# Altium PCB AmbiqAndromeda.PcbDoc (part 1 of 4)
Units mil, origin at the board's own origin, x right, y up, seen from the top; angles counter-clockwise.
Board outline 4055.04 x 2407.2 mil, 6 copper layers (Layer 1, Layer 2, Layer 3, Layer 4, Layer 5, Layer 6), stack 76.457 mil thick; 255 components, 215 nets, 1186 pads, 683 vias.
Unrouted connection lines stored in the file: 258.
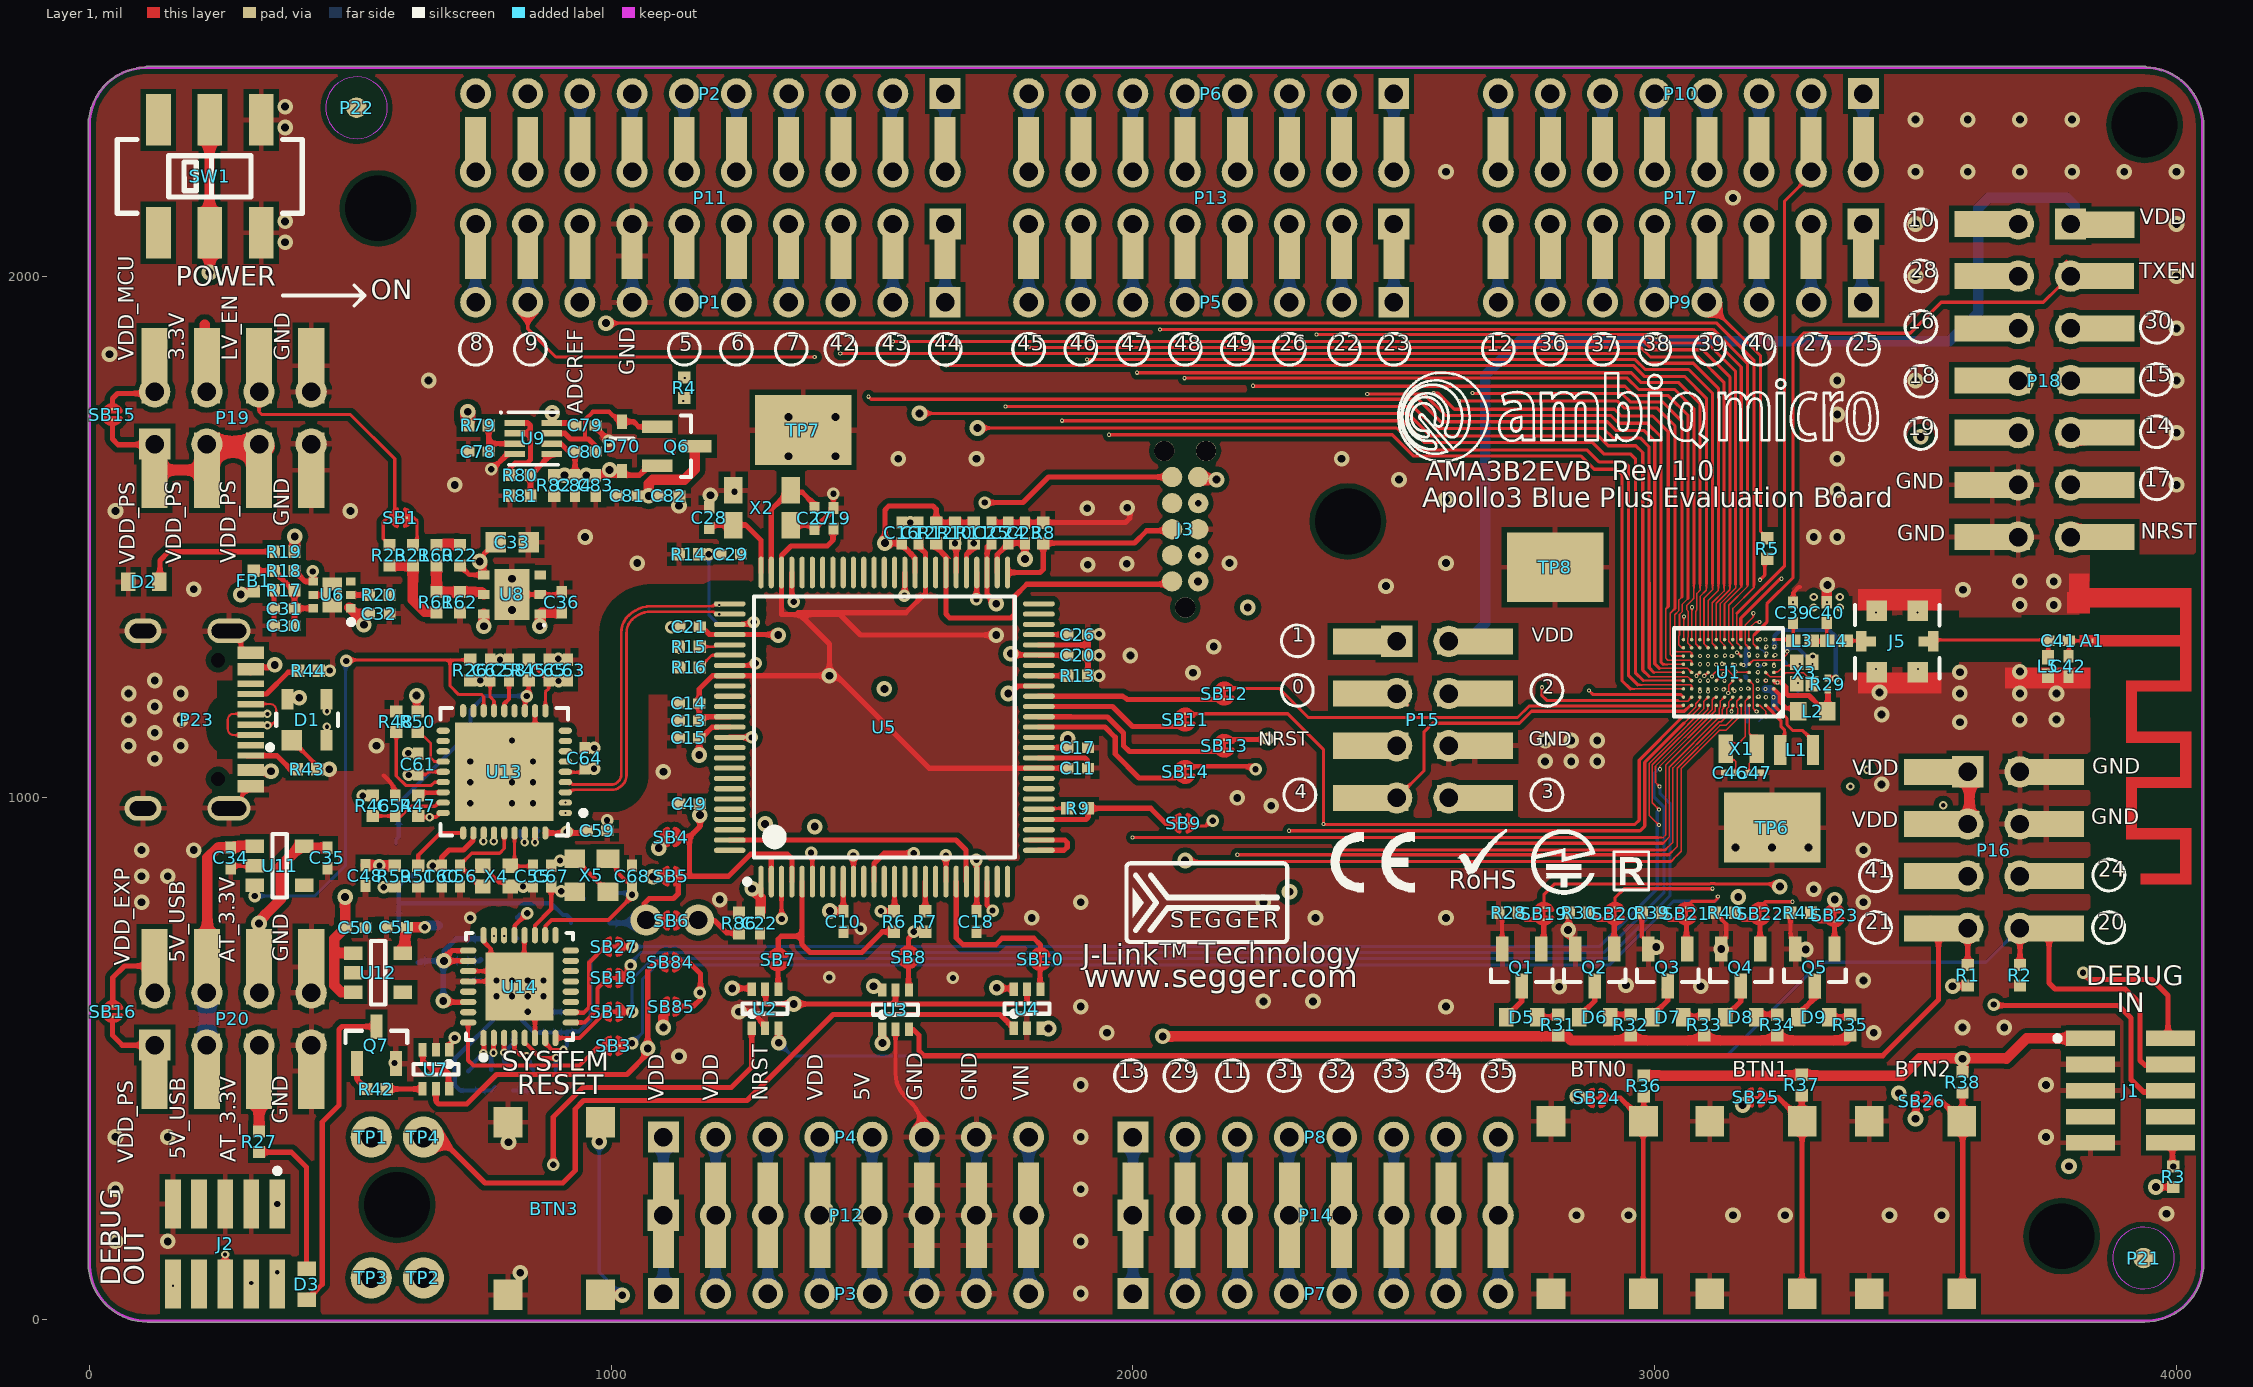
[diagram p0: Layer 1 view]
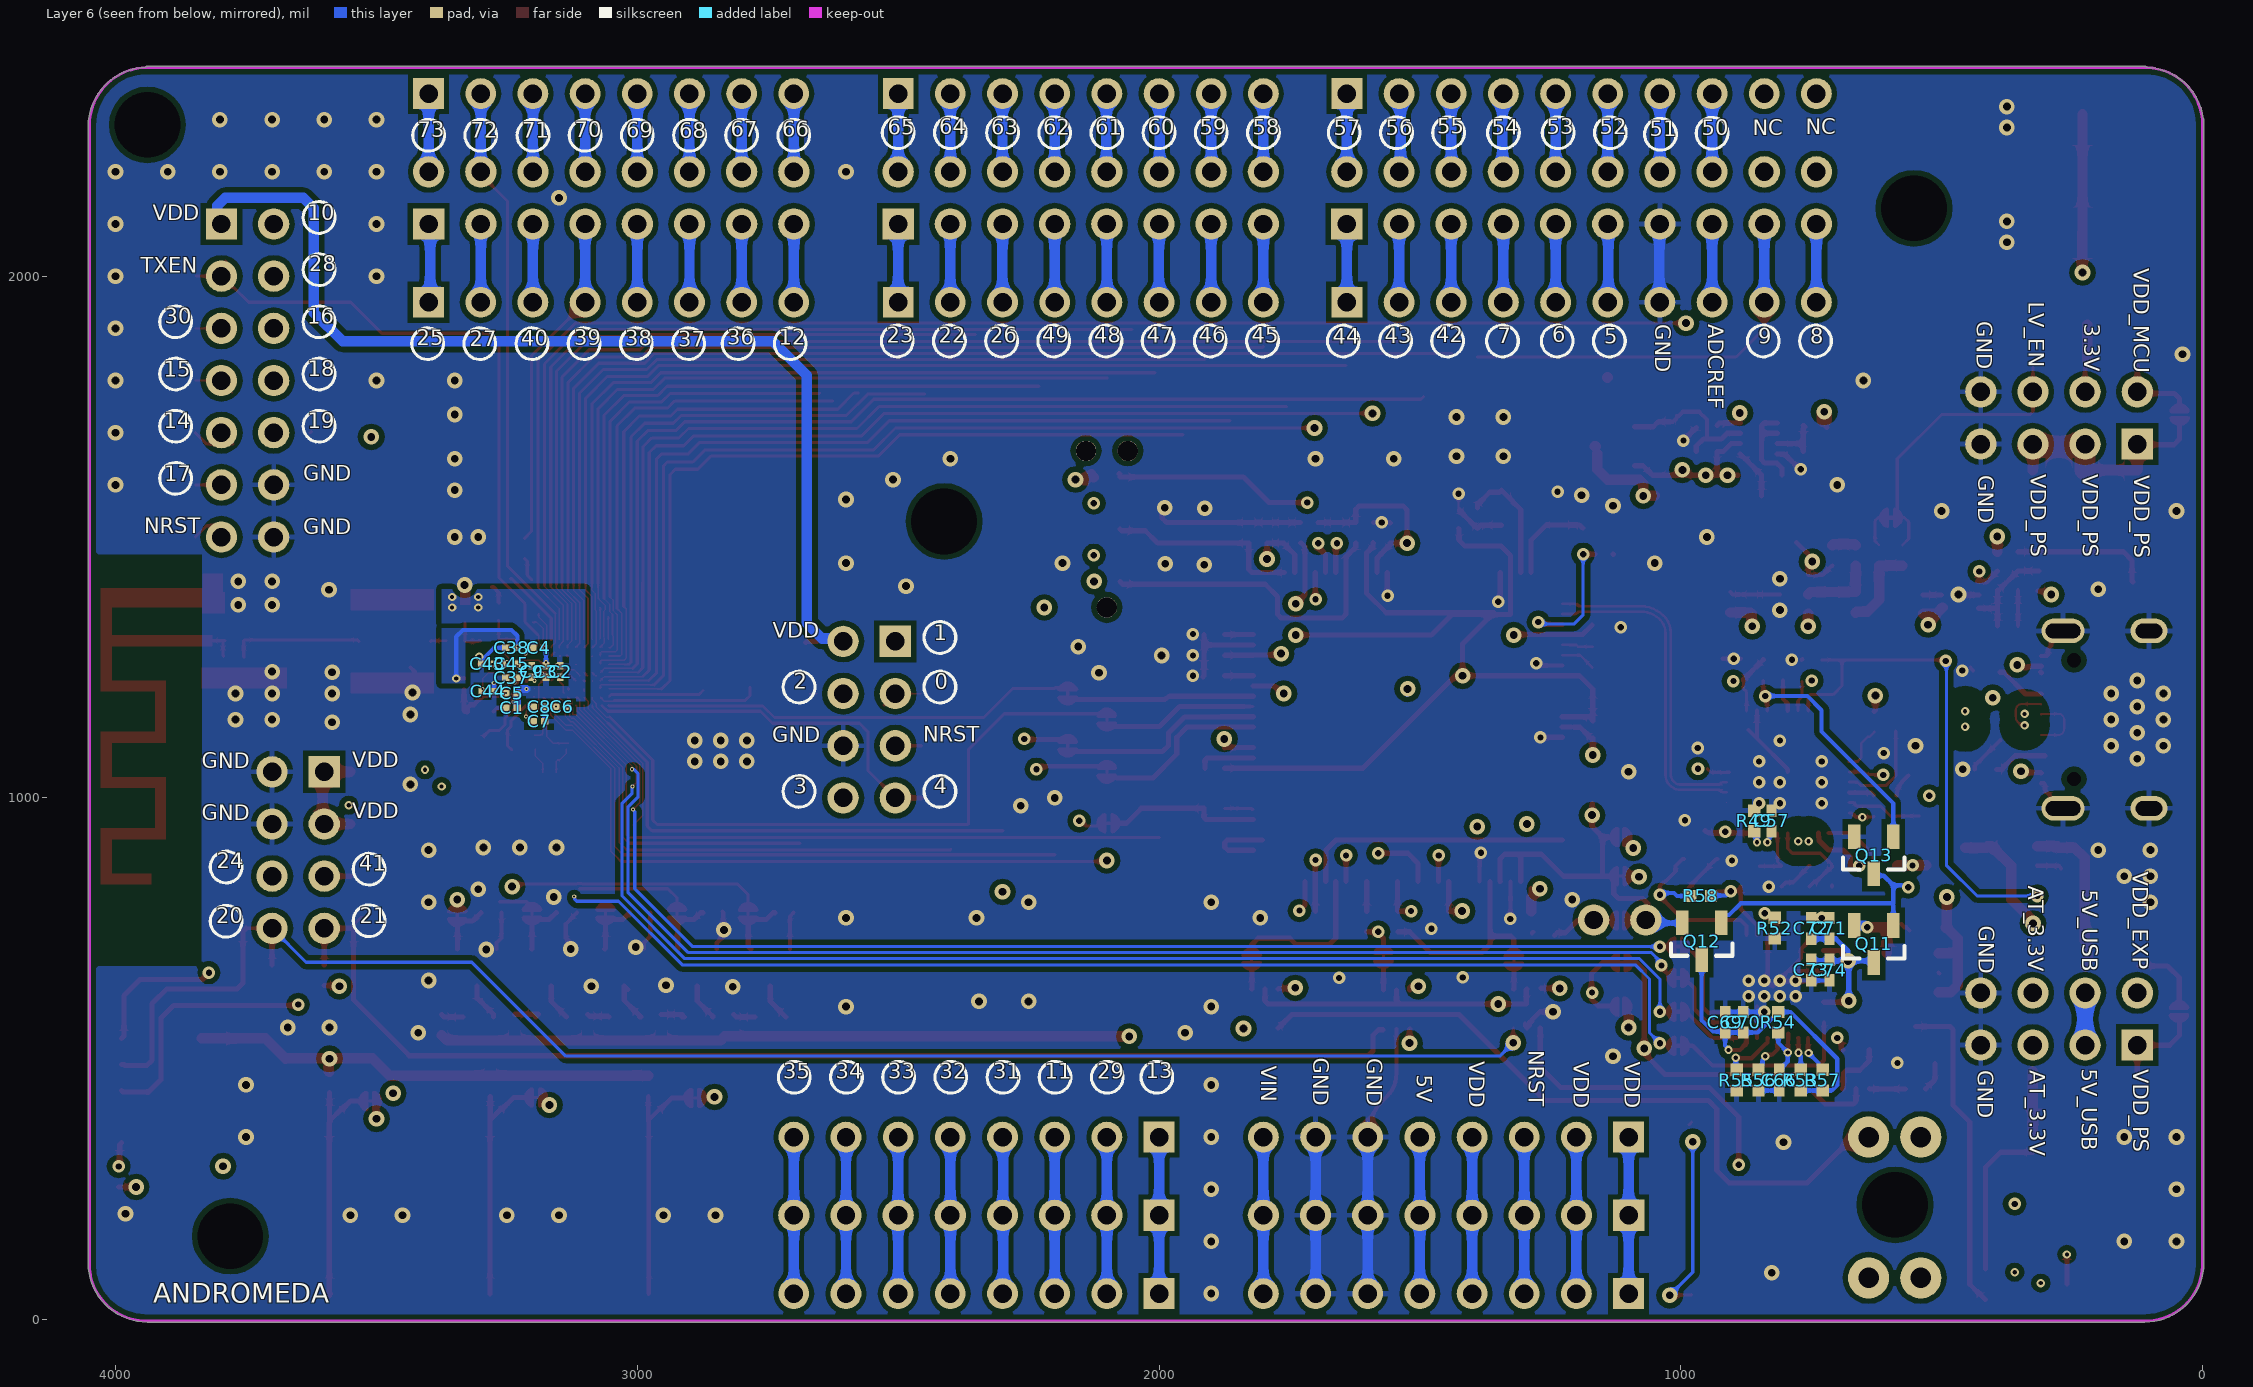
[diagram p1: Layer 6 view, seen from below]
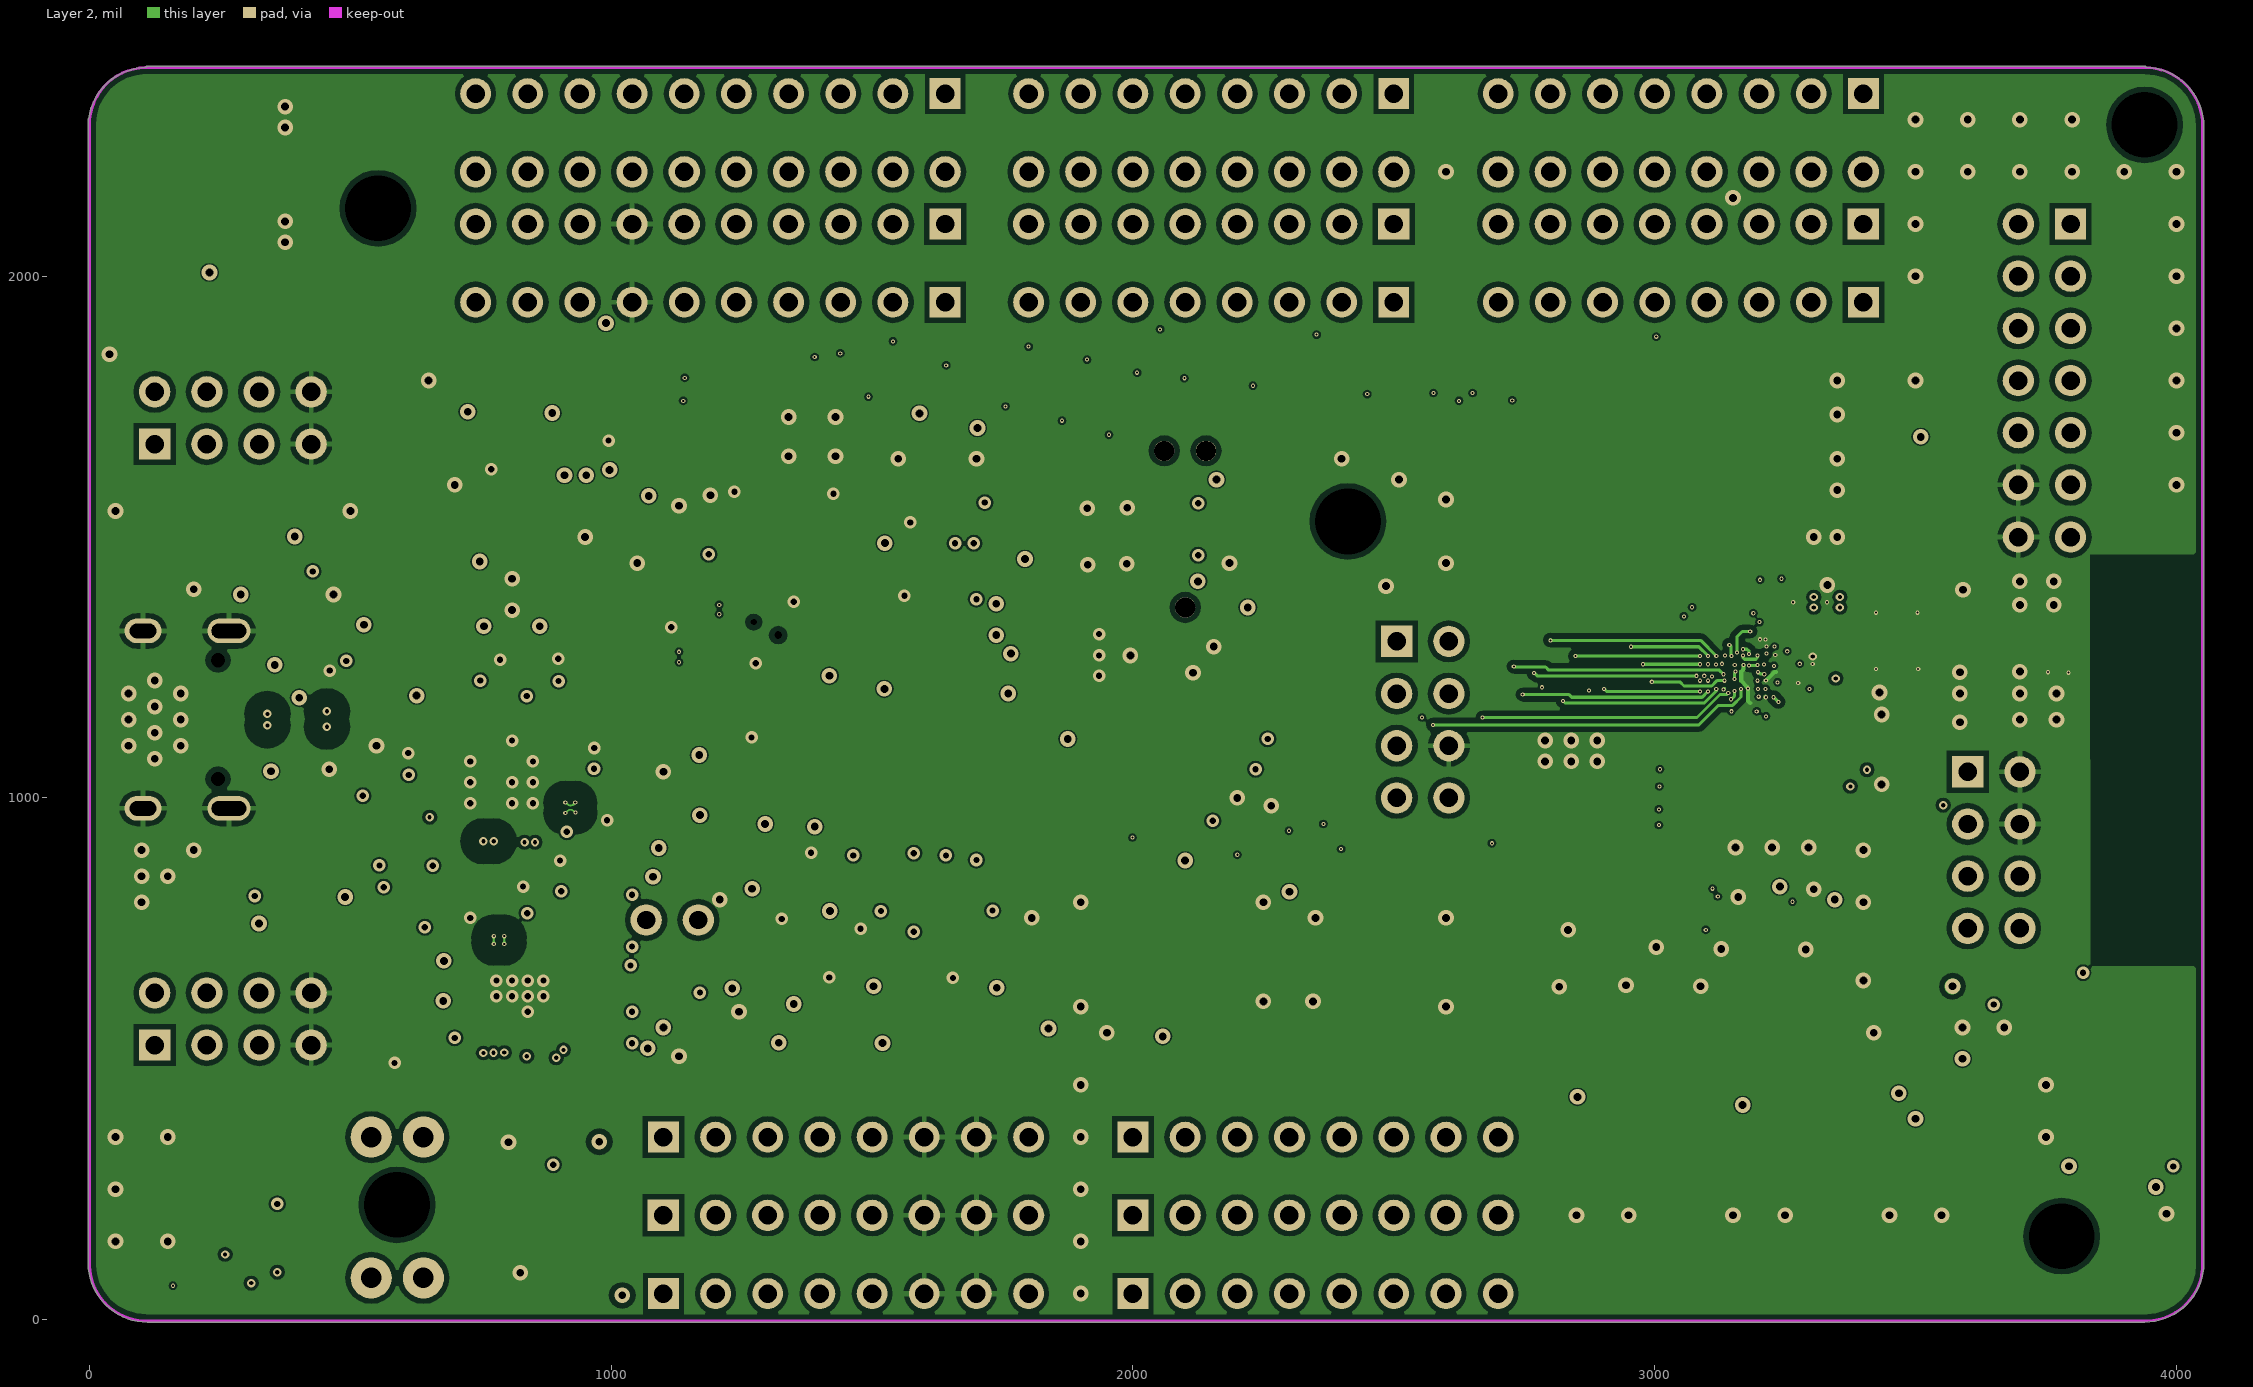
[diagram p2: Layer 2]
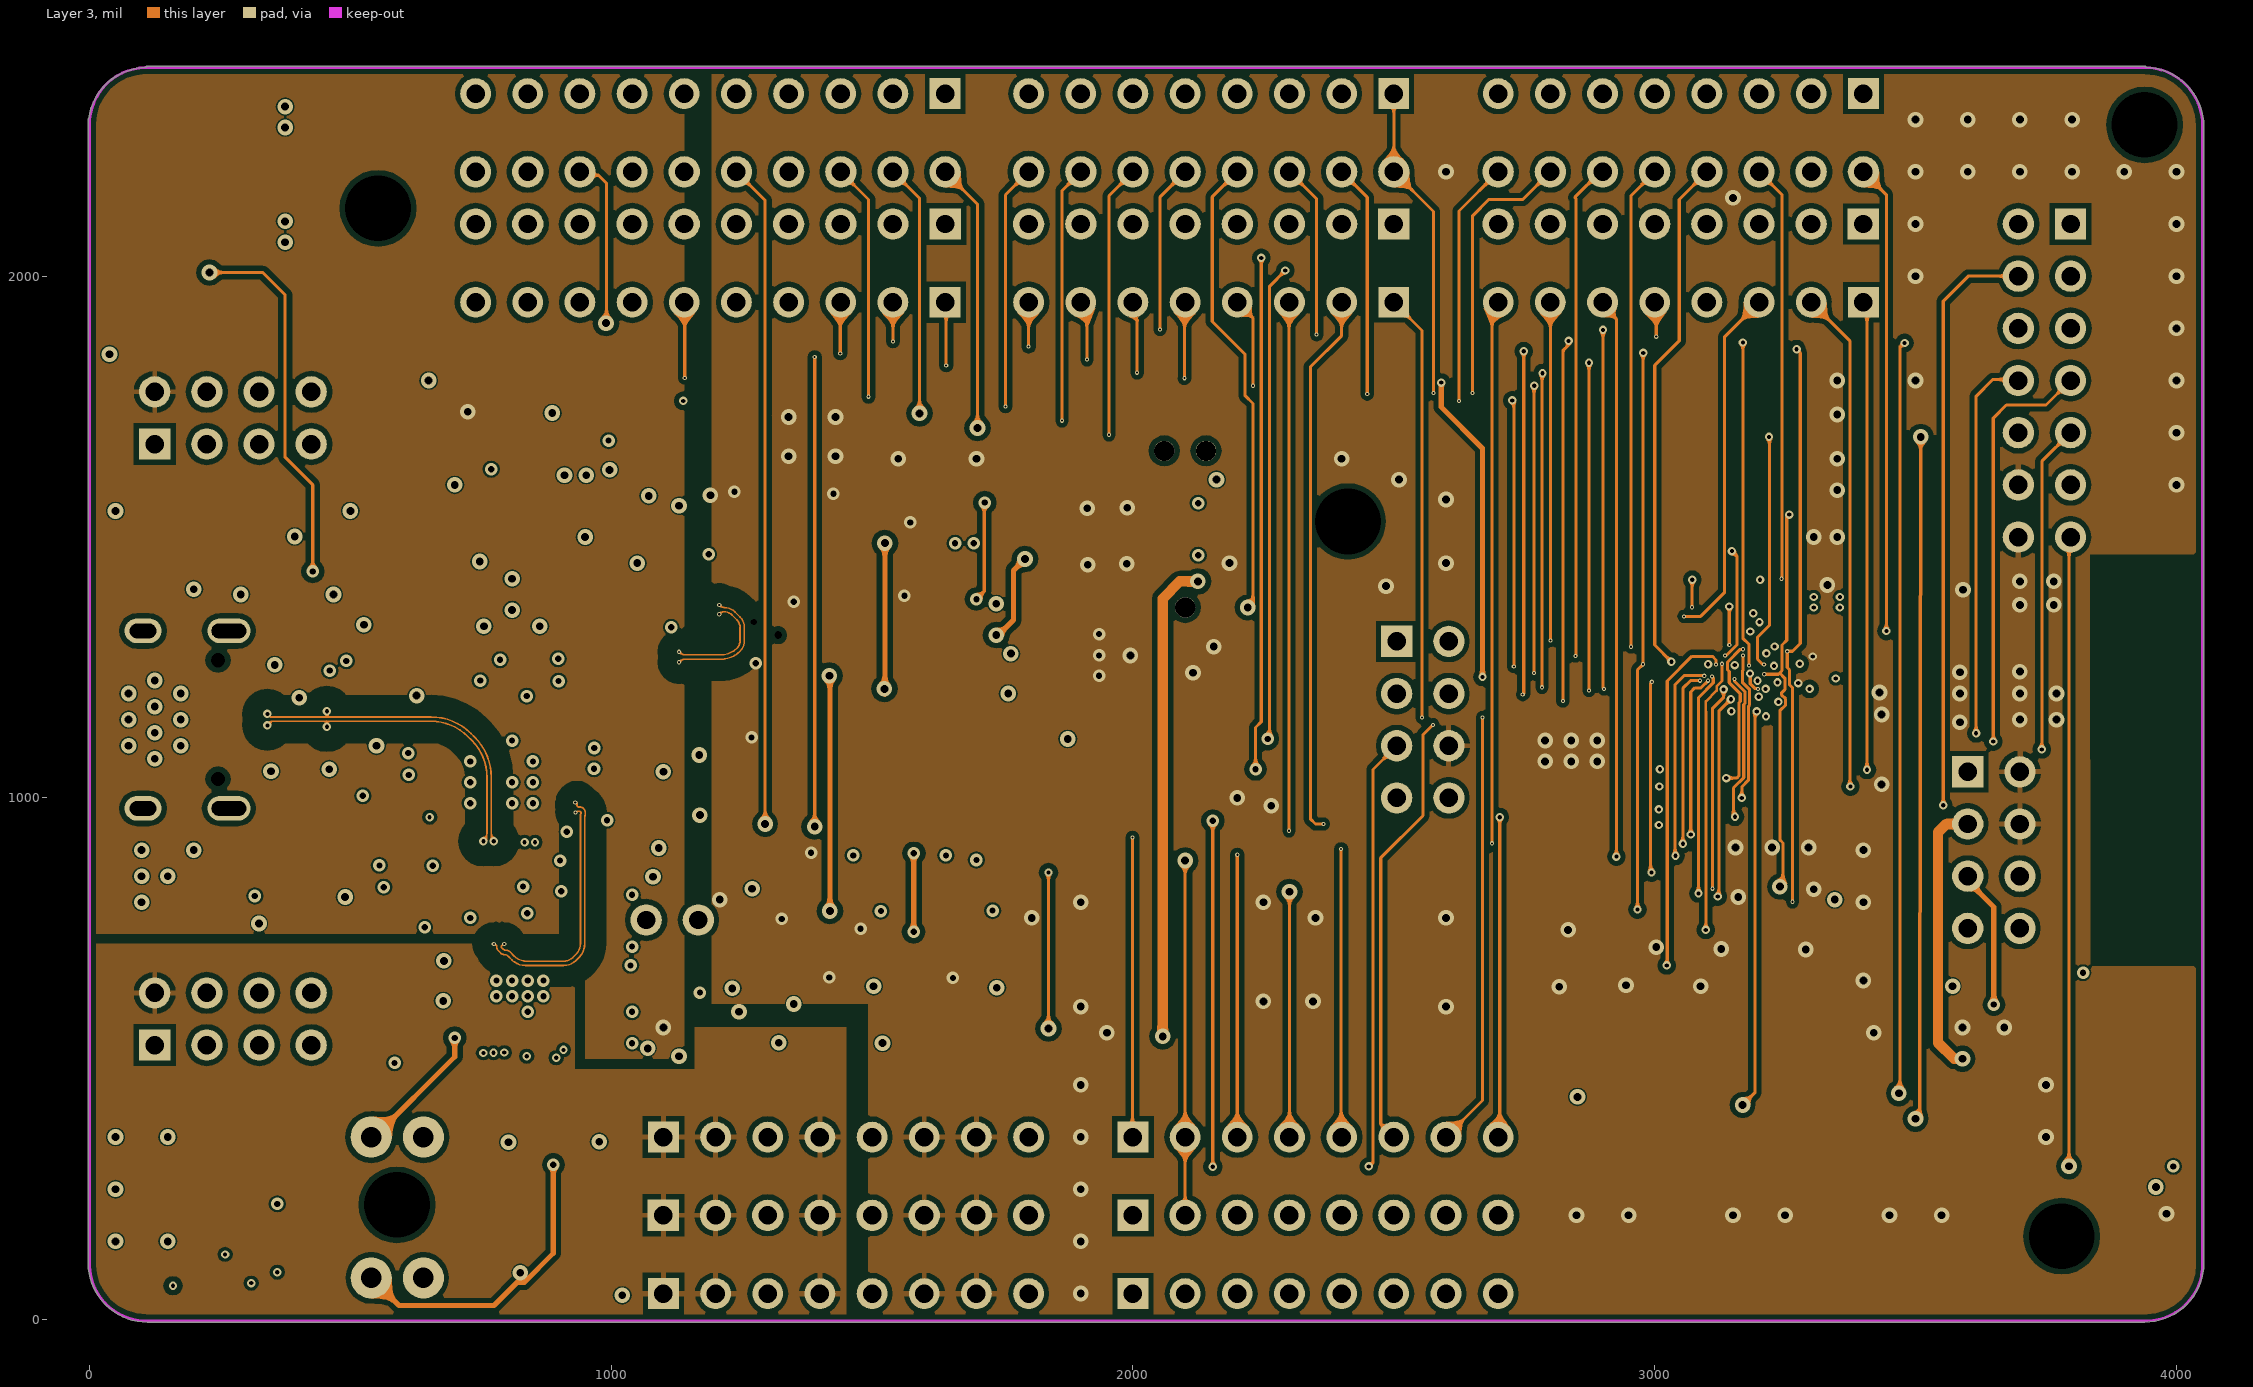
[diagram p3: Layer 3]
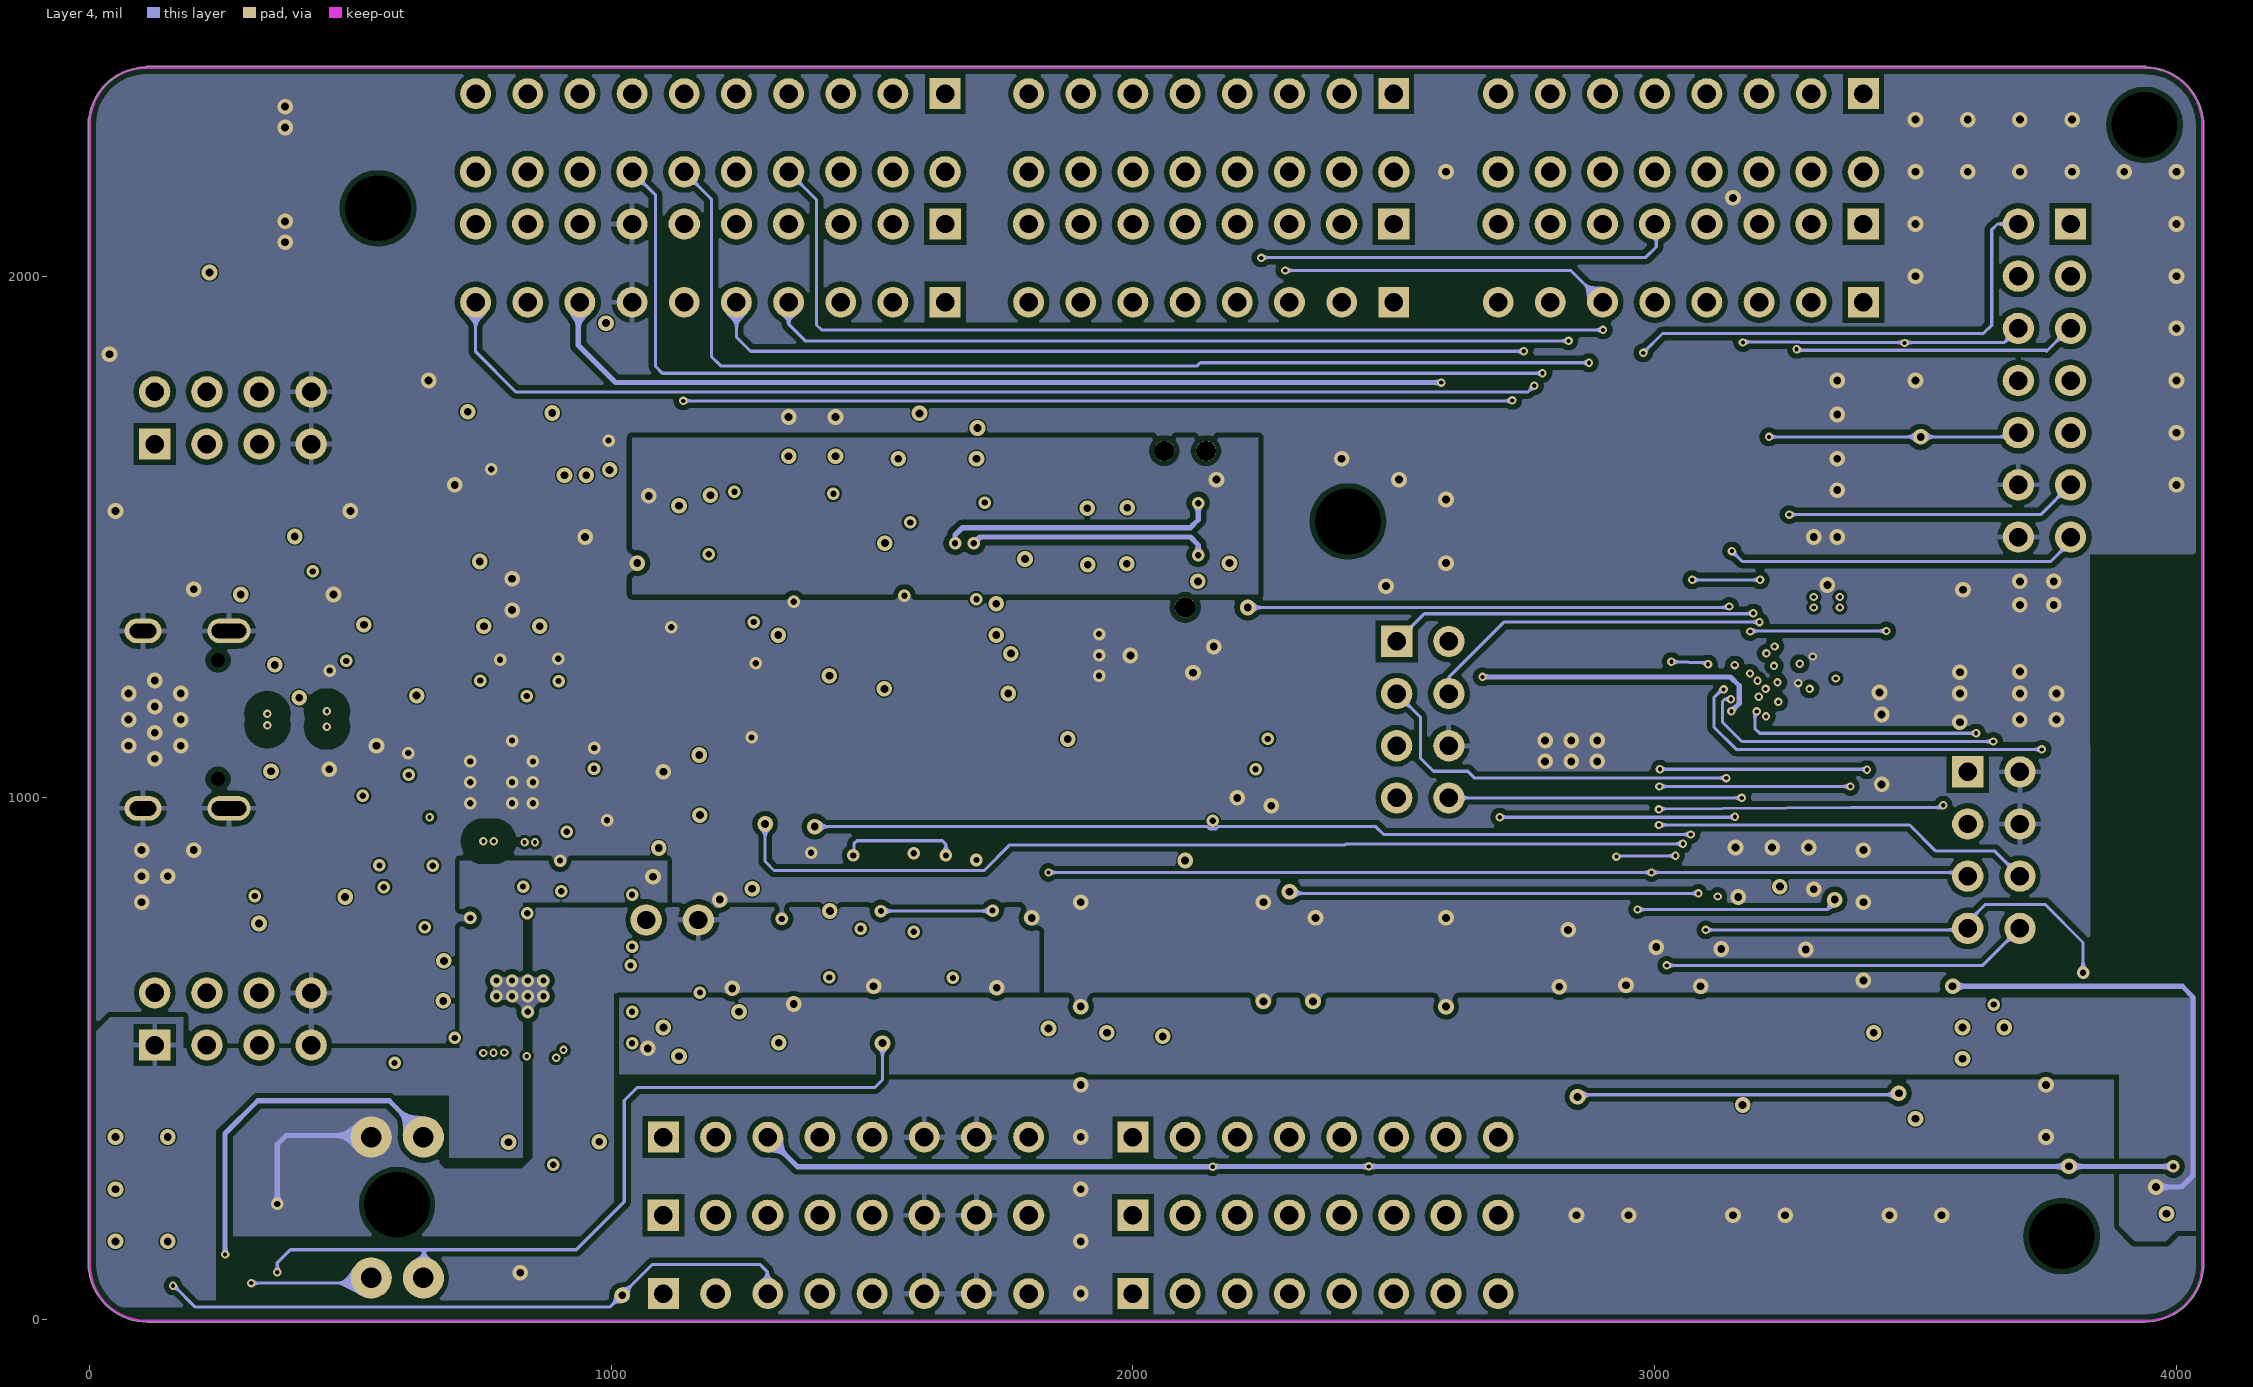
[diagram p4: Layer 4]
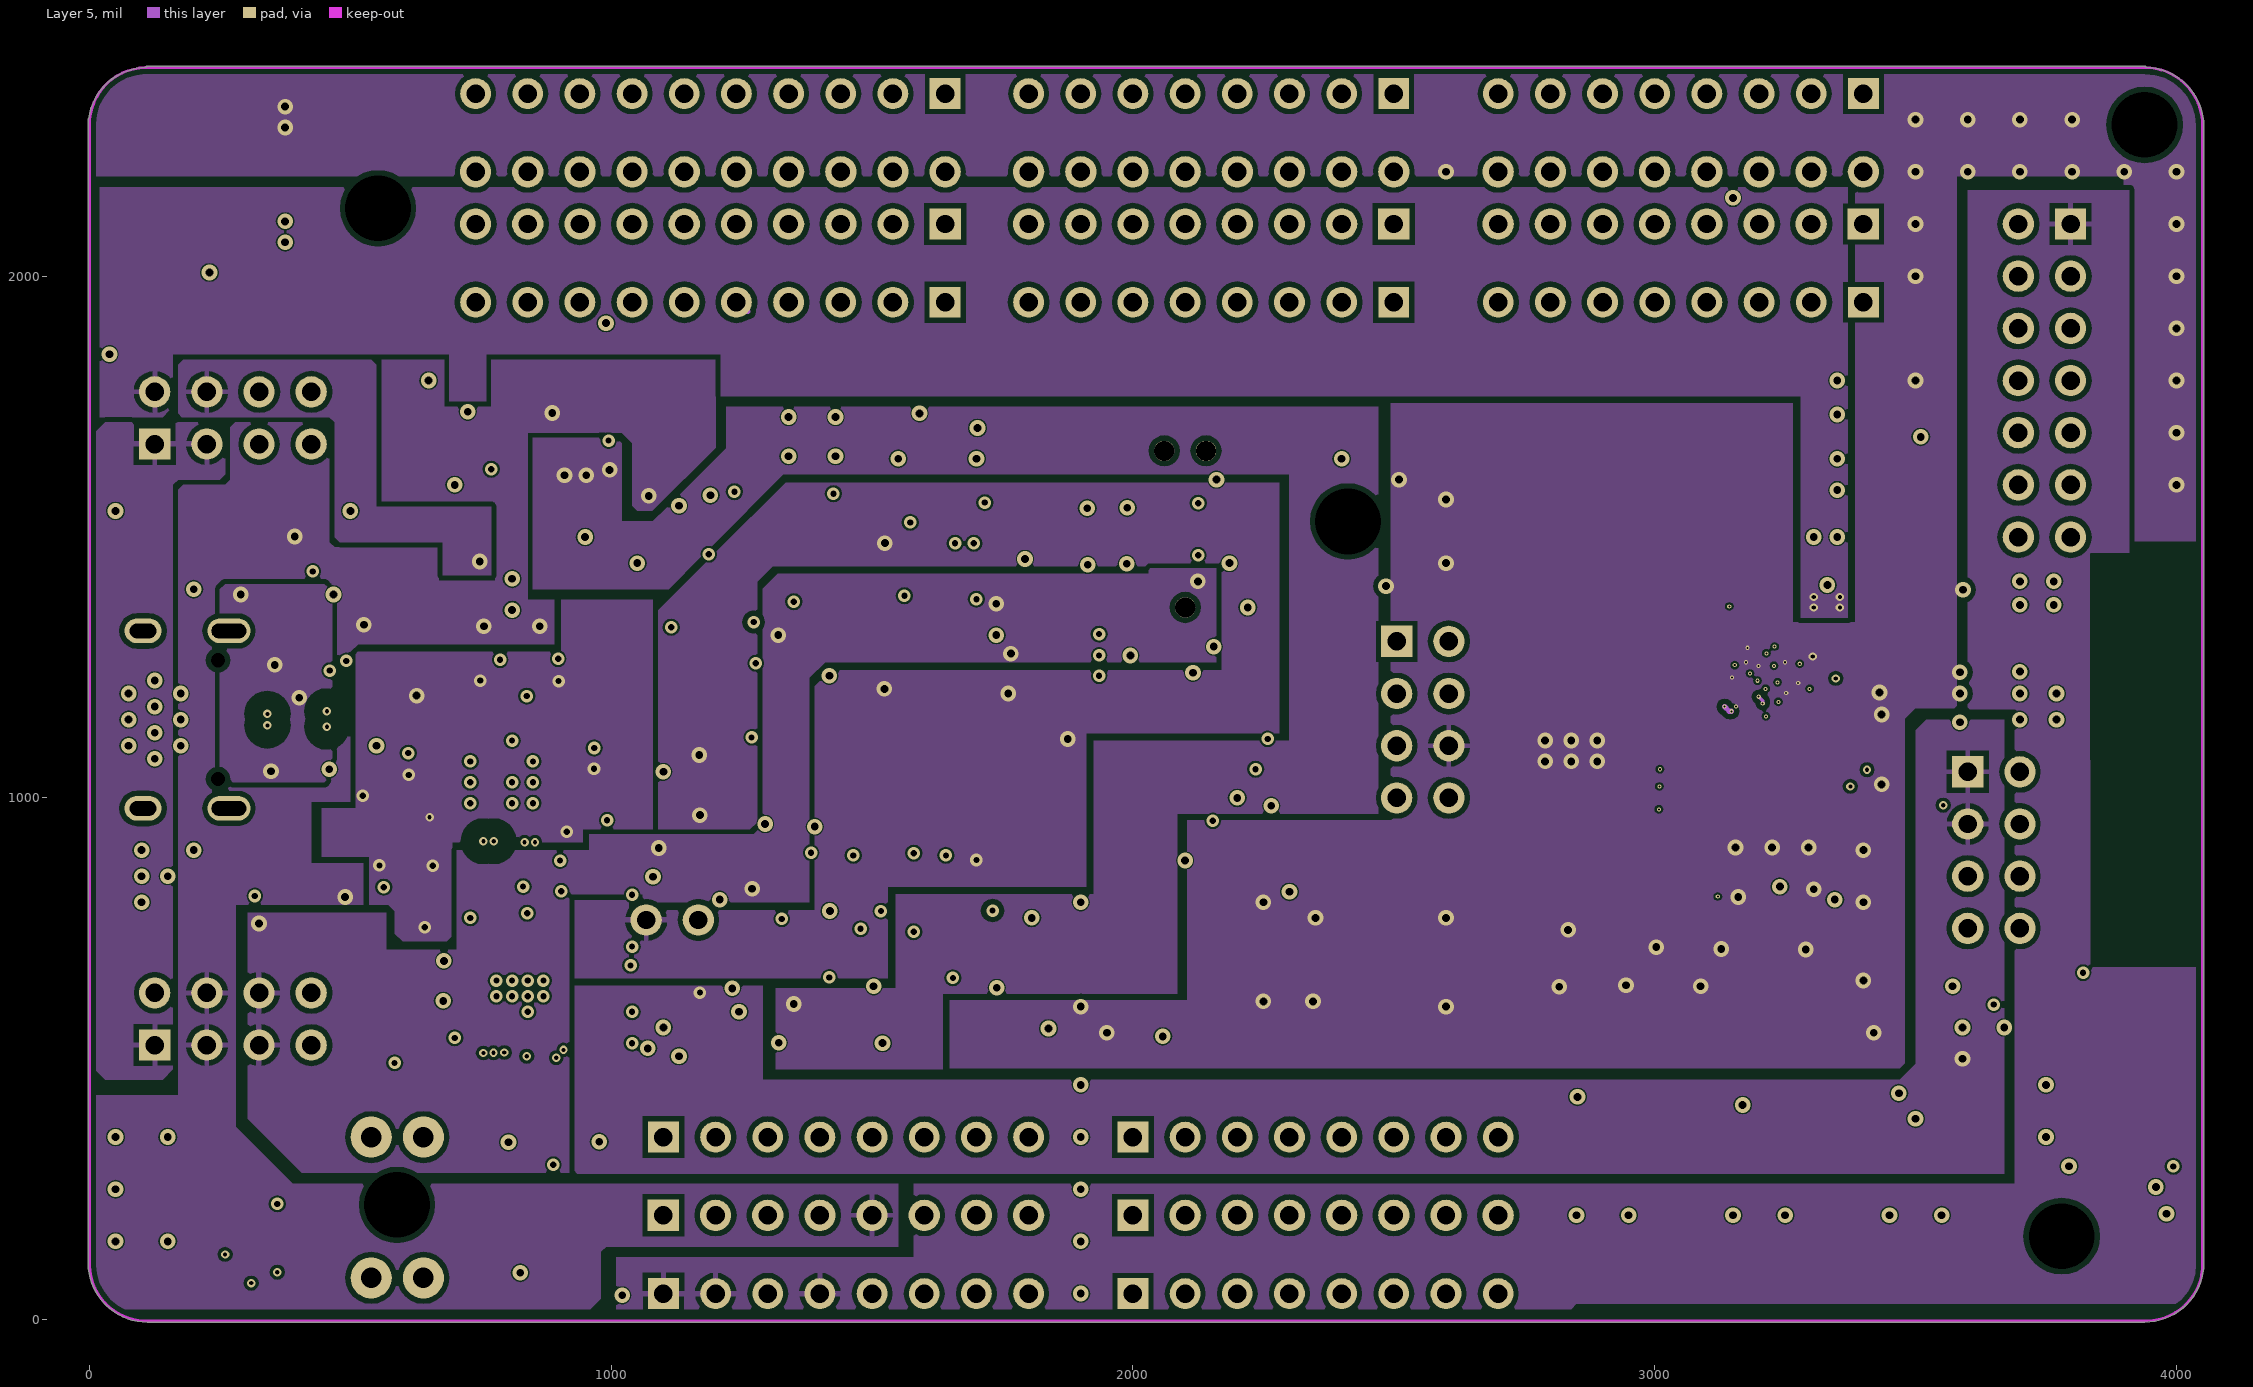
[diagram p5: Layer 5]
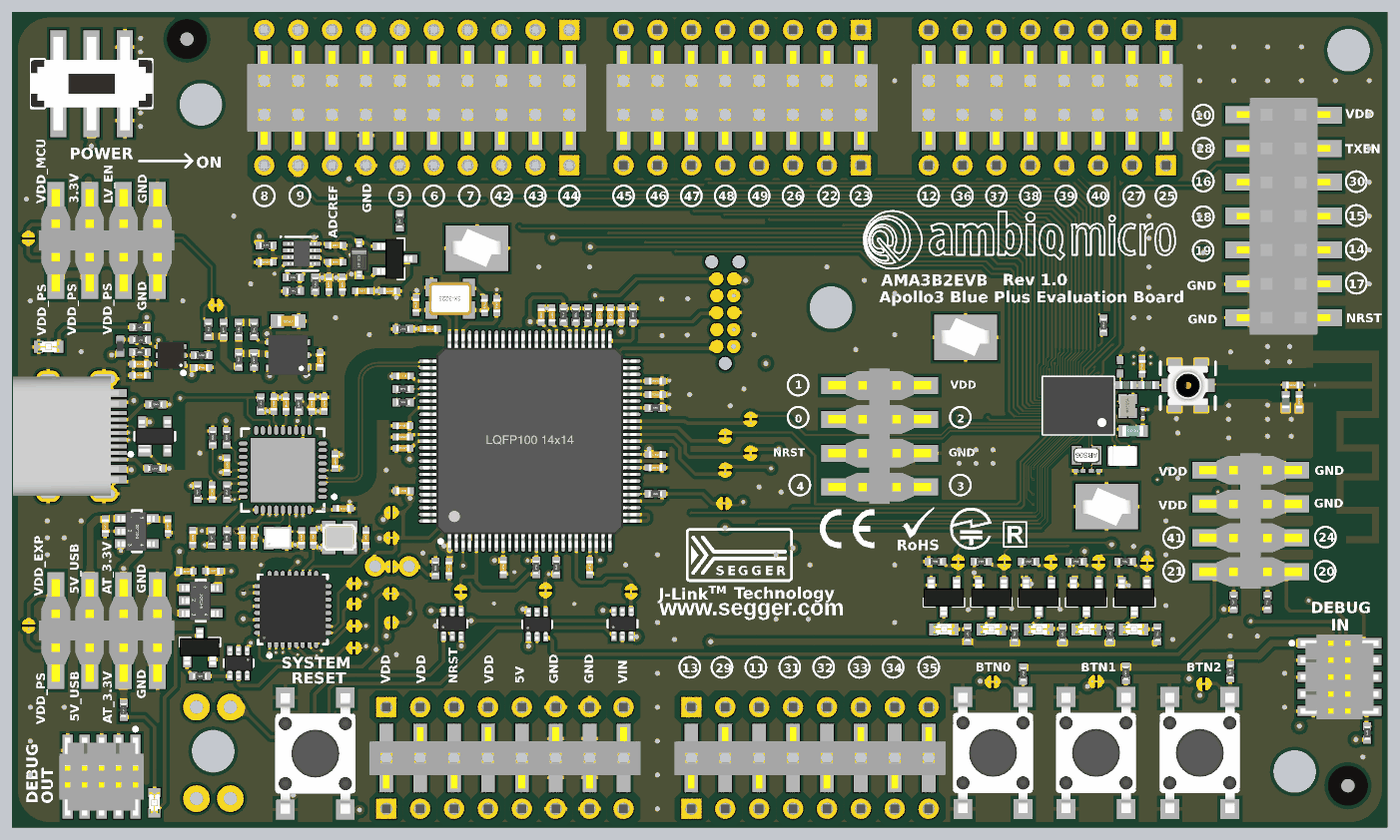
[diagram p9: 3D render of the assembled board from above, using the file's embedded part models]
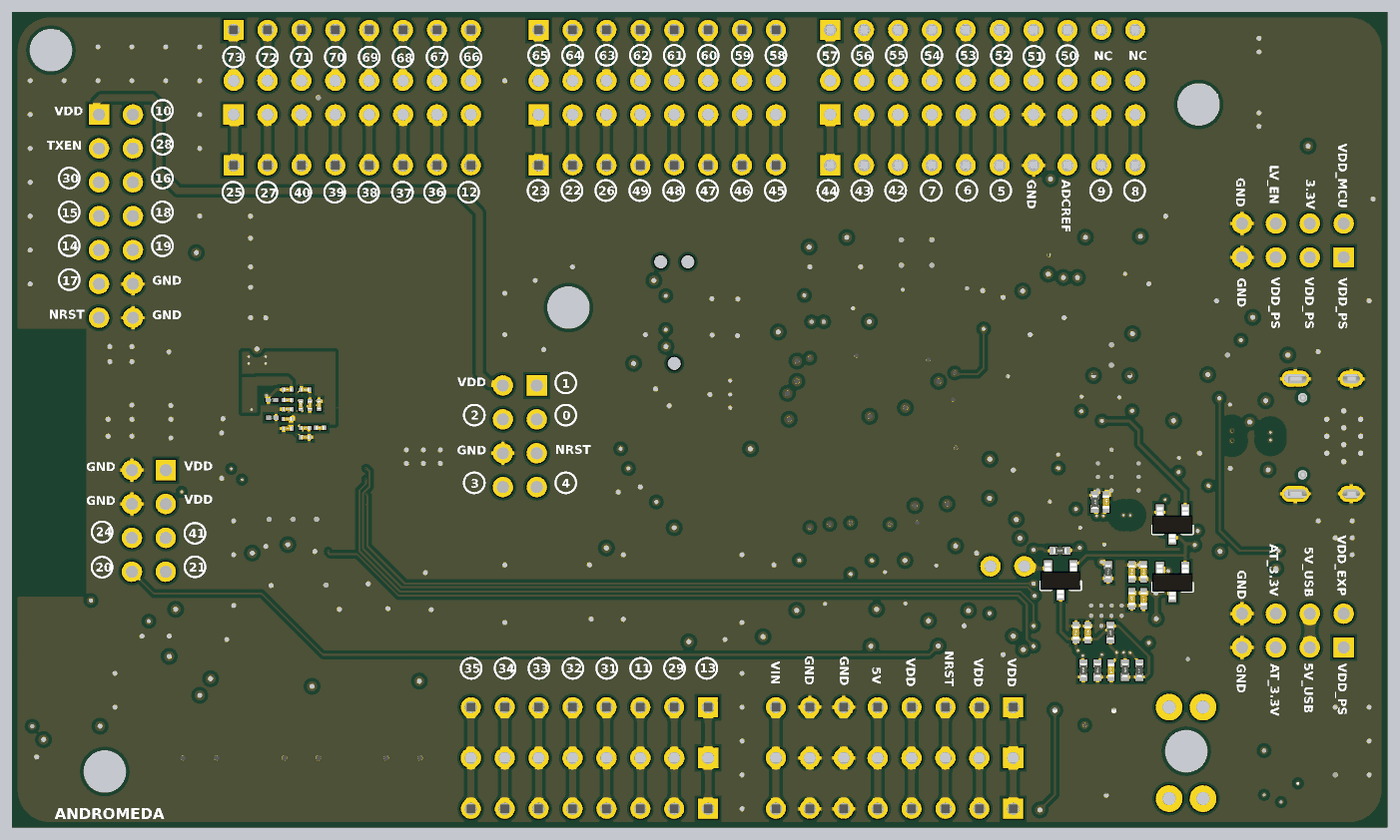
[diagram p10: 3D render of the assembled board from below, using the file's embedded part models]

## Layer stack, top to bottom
Top Solder: solder mask 0.7, Solder Resist, Dk 3.8
Layer 1: signal copper 1.3778
Dielectric 1: prepreg 2.9528, FR4, Dk 4.2
Layer 2: signal copper 0.7087
Dielectric 4: prepreg 2.9528, FR4, Dk 4.2
Layer 3: signal copper 0.7087
Dielectric 3: core 59.0551, FR4, Dk 4.2
Layer 4: signal copper 0.7087
Dielectric 5: prepreg 2.9528, FR4, Dk 4.2
Layer 5: signal copper 0.7087
Dielectric 2: prepreg 2.9528, FR4, Dk 4.2
Layer 6: signal copper 1.3778
Bottom Solder: solder mask 0.7, Solder Resist, Dk 3.8

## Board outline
-2.37,108.68 ccw(c110.99,108.68) 110.99,-4.68 ccw(c110.99,-2.17) 111.06,-4.68 3939.15,-4.53 3939.16,-4.53 ccw(c3939.15,108.83) 4052.51,108.83 ccw(c4049.99,108.83) 4052.51,108.83 4052.35,2286.79 ccw(c4049.84,2286.99) 4052.35,2286.99 ccw(c3938.99,2286.99) 3941.49,2400.32 ccw(c3938.99,2400) 3938.99,2402.52 110.84,2402.52 ccw(c110.84,2400) 108.33,2400.17 ccw(c110.84,2286.83) -1.5,2302.03 ccw(c-0.01,2300) -2.53,2300

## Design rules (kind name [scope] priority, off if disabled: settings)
Clearance Clearance_1 [IsMicroVia] p1: gap=4 ignorepadtopadclearanceinfootprint=TRUE except(0: THPad-Hole Via-Hole Fill-Hole Poly-Hole Region-Hole Text-Hole; 3: Arc-Arc Arc-Track Arc-SMDPad Arc-THPad Arc-Via Arc-Hole Track-Track Track-SMDPad Track-THPad Track-Via Track-Hole SMDPad-SMDPad SMDPad-THPad SMDPad-Via SMDPad-Hole THPad-THPad THPad-Via Via-Via; 10: Arc-Text Track-Text SMDPad-Text THPad-Text Via-Text Fill-Text Poly-Text Region-Text Text-Text)
Clearance "TLINE GND Clearance" [InDifferentialPair('AT_USB') or InDifferentialPair('DFSD') or InNetClass('TLIN50') or InDifferentialPair('FTDI_USB')or InDifferentialPair('USB') vs InPolygon] p2: gap=40 ignorepadtopadclearanceinfootprint=TRUE except(0: Arc-Hole Track-Hole SMDPad-Hole THPad-Hole Via-Hole Fill-Hole Poly-Hole Region-Hole Text-Hole; 3: Arc-Arc Arc-Track Arc-SMDPad Arc-Via Track-Track Track-SMDPad Track-Via SMDPad-SMDPad SMDPad-Via; 4: Via-Via; 6: Arc-THPad Track-THPad SMDPad-THPad; 10: Arc-Text Track-Text SMDPad-Text THPad-THPad THPad-Via THPad-Text Via-Text Fill-Text Poly-Text Region-Text Text-Text)
Clearance "Polygon Clearance" [InPolygon] p3: gap=10 ignorepadtopadclearanceinfootprint=TRUE except(0: Arc-Hole Track-Hole SMDPad-Hole THPad-Hole Via-Hole Fill-Hole Poly-Hole Region-Hole Text-Hole; 3: Arc-Arc Arc-Track Arc-SMDPad Arc-Via Track-Track Track-SMDPad Track-Via SMDPad-SMDPad SMDPad-Via; 4: Via-Via; 6: Arc-THPad Track-THPad SMDPad-THPad)
Clearance 3 [OnLayer('Keep-Out Layer') vs NOT InComponent('A1')] p4: gap=10 ignorepadtopadclearanceinfootprint=TRUE except(0: Arc-Hole Track-Hole SMDPad-Hole THPad-Hole Via-Hole Fill-Hole Poly-Hole Region-Hole Text-Hole; 3: Arc-Arc Arc-Track Arc-SMDPad Arc-Via Track-Track Track-SMDPad Track-Via SMDPad-SMDPad SMDPad-Via; 4: SMDPad-Fill SMDPad-Poly SMDPad-Region Via-Via; 6: Arc-THPad Track-THPad SMDPad-THPad Via-Fill Via-Poly Via-Region Fill-Fill Fill-Poly Fill-Region Poly-Poly Poly-Region Region-Region; 20: Arc-Fill Arc-Poly Arc-Region Track-Fill Track-Poly Track-Region)
Clearance [All] p5: gap=4 ignorepadtopadclearanceinfootprint=TRUE except(0: THPad-Hole Via-Hole Fill-Hole Poly-Hole Region-Hole Text-Hole; 3: Arc-Arc Arc-Track Arc-SMDPad Arc-THPad Arc-Via Track-Track Track-SMDPad Track-THPad Track-Via SMDPad-SMDPad SMDPad-THPad SMDPad-Via THPad-THPad THPad-Via Via-Via; 6: Arc-Hole Track-Hole SMDPad-Hole; 10: Arc-Text Track-Text SMDPad-Text THPad-Text Via-Text Fill-Text Poly-Text Region-Text Text-Text)
ComponentClearance ComponentClearance_1 [InComponent('P2') OR InComponent('P10') OR InComponent('P6') OR InComponent('P12')  OR InComponent('P14') vs InComponent('P11') OR InComponent('P13')  OR InComponent('P17') oR InComponent('P3')  OR InComponent('P7')] p1: gap=0 collisioncheckmode=3 verticalgap=10 showdistances=FALSE
ComponentClearance [All] p2: gap=10 collisioncheckmode=3 verticalgap=10 showdistances=FALSE
DiffPairsRouting USB_AT [InDifferentialPair('AT_USB') or InDifferentialPair('DFSD') or InDifferentialPair('FTDI_USB') or InDifferentialPair('USB')] p1: maxlimit=5 minlimit=5 mostfreqgap=5 toplayer_minwidth=2.93 toplayer_maxwidth=5.15 toplayer_prefwidth=3.91 midlayer1_minwidth=2.44 midlayer1_maxwidth=3.27 midlayer1_prefwidth=3.24 midlayer2_minwidth=1.6 midlayer2_maxwidth=3.24 midlayer2_prefwidth=3.24 midlayer3_minwidth=2.16 midlayer3_maxwidth=3.24 midlayer3_prefwidth=3.24 midlayer4_minwidth=3.09 midlayer4_maxwidth=3.24 midlayer4_prefwidth=3.24 bottomlayer_minwidth=2.93 bottomlayer_maxwidth=5.26 bottomlayer_prefwidth=3.91 impedanceprofiledriven=TRUE impedanceprofileid={EFAE9810-7C72-4CE3-B640-AD99D6EDDCE3} impedanceprofilevalue=90.000000 maxuncoupledlength=100
HoleSize [All] p1: absolutevalues=TRUE maxlimit=1000 minlimit=1 maxpercent=80.000 minpercent=20.000
HoleToHoleClearance HoleToHoleClearance_1 [IsMicroVia vs IsMicroVia] p1: gap=6 allowstackedmicrovias=TRUE
HoleToHoleClearance [All] p2: gap=8 allowstackedmicrovias=TRUE
MatchedLengths "Schematic Matched Net Lengths_9" [InNet('FTDI_USB_P')] p1: tolerance=50 checknetsindiffpair=TRUE checkdiffpairvsdiffpair=FALSE checkxsignals=FALSE checkothers=FALSE
MatchedLengths "Schematic Matched Net Lengths_8" [InNet('AT_USB_P')] p2: tolerance=50 checknetsindiffpair=TRUE checkdiffpairvsdiffpair=FALSE checkxsignals=FALSE checkothers=FALSE
MatchedLengths "Schematic Matched Net Lengths_5" [InNet('AT_USB_N')] p3: tolerance=50 checknetsindiffpair=TRUE checkdiffpairvsdiffpair=FALSE checkxsignals=FALSE checkothers=FALSE
MatchedLengths "Schematic Matched Net Lengths_4" [InNet('FTDI_USB_N')] p4: tolerance=50 checknetsindiffpair=TRUE checkdiffpairvsdiffpair=FALSE checkxsignals=FALSE checkothers=FALSE
MatchedLengths "Schematic Matched Net Lengths_7" [InNet('USB_N')] p5: tolerance=50 checknetsindiffpair=TRUE checkdiffpairvsdiffpair=FALSE checkxsignals=FALSE checkothers=FALSE
MatchedLengths "Schematic Matched Net Lengths_6" [InNet('USB_P')] p6: tolerance=50 checknetsindiffpair=TRUE checkdiffpairvsdiffpair=FALSE checkxsignals=FALSE checkothers=FALSE
MatchedLengths "Schematic Matched Net Lengths" [InNet('DFSD_N')] p7: tolerance=50 checknetsindiffpair=TRUE checkdiffpairvsdiffpair=FALSE checkxsignals=FALSE checkothers=FALSE
MatchedLengths "Schematic Matched Net Lengths_3" [InNet('DFSD_P')] p8: tolerance=50 checknetsindiffpair=TRUE checkdiffpairvsdiffpair=FALSE checkxsignals=FALSE checkothers=FALSE
MatchedLengths "Schematic Matched Net Lengths_2" [InNet('AT_USB_N')] p9: tolerance=50 checknetsindiffpair=TRUE checkdiffpairvsdiffpair=FALSE checkxsignals=FALSE checkothers=FALSE
MatchedLengths "Schematic Matched Net Lengths_1" [InNet('AT_USB_P')] p10: tolerance=50 checknetsindiffpair=TRUE checkdiffpairvsdiffpair=FALSE checkxsignals=FALSE checkothers=FALSE
MinimumSolderMaskSliver [All] p1 off: minsoldermaskwidth=10
PlaneClearance [All] p1: clearance=8
PlaneConnect [All] p1: planeconnectstyle=Direct reliefexpansion=20 reliefentries=4 reliefconductorwidth=10 reliefairgap=10
PolygonConnect PolygonConnect_1 [IsVia] p1: connectstyle=Direct reliefconductorwidth=10 reliefentries=4 polygonreliefangle="90 Angle" airgapwidth=10
PolygonConnect [All] p2: connectstyle=Relief reliefconductorwidth=10 reliefentries=4 polygonreliefangle="90 Angle" airgapwidth=10
RoutingVias uVias [InDrillLayerPair('[UVIA] Layer 1 - Layer 2') OR InDrillLayerPair('[UVIA] Layer 2 - Layer 3') OR InDrillLayerPair('[UVIA] Layer 4 - Layer 5') OR InDrillLayerPair('[UVIA] Layer 5 - Layer 6')] p1: holewidth=4 width=8 viastyle="Through Hole" minholewidth=4 minwidth=8 maxholewidth=4 maxwidth=8
RoutingVias [InDrillLayerPair('Layer 1 - Layer 6') OR InDrillLayerPair('Layer 3 - Layer 4')] p2: holewidth=15 width=30 viastyle="Through Hole" minholewidth=8 minwidth=16 maxholewidth=100 maxwidth=200
ShortCircuit [InComponent('A1') vs InNet('GND')] p1: allowed=TRUE
SilkToSilkClearance [All] p1 off: silktosilkclearance=10
SilkToSolderMaskClearance [IsPad] p1 off: minsilkscreentomaskgap=10 clearancetoexposedcopper=TRUE
SolderMaskExpansion [All] p1: expansion=4
Width RF_TLIN [InNetClass('TLIN50')] p1: maxlimit=6.38 minlimit=2.81 preferedwidth=3.69 toplayer_minwidth=4.33 toplayer_maxwidth=6.25 toplayer_prefwidth=4.33 midlayer1_minwidth=3.37 midlayer1_maxwidth=3.71 midlayer2_maxwidth=3.69 midlayer3_maxwidth=3.68 midlayer3_prefwidth=3.68 midlayer4_minwidth=3.68 midlayer4_maxwidth=4.52 midlayer4_prefwidth=3.68 bottomlayer_minwidth=4.33 bottomlayer_prefwidth=4.33 impedanceprofiledriven=TRUE impedanceprofileid={4AD285A2-0FED-4AA8-8DF2-44B4B48F9EBB} impedanceprofilevalue=50.000000 minimp=50.000000 maximp=50.000000 favimp=50.000000
Width [All] p2: maxlimit=100 minlimit=3 preferedwidth=8 minimp=50.000000 maximp=50.000000 favimp=50.000000
20 further rules are at their usual default settings.

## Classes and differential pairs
component class [10]USBSPIBridge: C48 C49 C66 C67 C68 C69 C70 C71 C72 C73 C74 Q11 Q12 Q13 R52 R53 R54 R55 R56 R57 R58 R59 SB3 SB17 SB18 SB27 U14 X5
component class [09]USBHub: C50 C51 C54 C55 C56 C57 C58 C59 C60 C61 C62 C63 C64 C65 R26 R45 R46 R47 R48 R49 R50 R51 U12 U13 X4
net class TLIN50: NetA1_1 NetC39_1 NetC40_1 NetC41_1 NetJ5_1
component class "[07]User Interface": BTN0 BTN1 BTN2 BTN3 D5 D6 D7 D8 D9 P21 P22 Q1 Q2 Q3 Q4 Q5 R28 R30 R31 R32 R33 R34 R35 R36 R37 R38 R39 R40 R41 SB19 SB20 SB21 SB22 SB23 SB24 SB25 SB26
component class "[05]Power Supply Tracker": C78 C79 C80 C81 C82 C83 C84 D70 Q6 R79 R80 R81 R82 SB84 SB85 U9
component class "[04]Power Supplies": C30 C31 C32 C33 C34 C35 C36 D1 D2 FB1 P19 P20 P23 R17 R18 R19 R20 R21 R22 R23 R43 R44 R60 R61 R62 SB1 SB15 SB16 SW1 U6 U8 U11
component class [01]MCU: A1 C1 C2 C3 C4 C5 C6 C7 C8 C9 C37 C38 C39 C40 C41 C42 C43 C44 C45 C46 C47 J5 L1 L2 L3 L4 L5 R1 R2 R3 R4 R5 R29 U1 X1 X3
component class "[06]J-Link OB Debugger": C10 C11 C12 C13 C14 C15 C16 C17 C18 C19 C20 C21 C22 C23 C24 C25 C26 C27 C28 C29 R6 R7 R8 R9 R10 R11 R12 R13 R14 R15 R16 SB4 SB5 SB6 SB7 SB8 SB9 SB10 SB11 SB12 SB13 SB14 U5 X2
component class "[08]Debug Headers and Support": D3 J1 J2 J3 Q7 R27 R42 R86 TP1 TP2 TP3 TP4 TP6 TP7 TP8 U2 U3 U4 U7
component class "[03]Breakout Headers": P1 P2 P3 P4 P5 P6 P7 P8 P9 P10
component class "[02]Arduino Headers": P11 P12 P13 P14 P15 P16 P17 P18
differential pair USB: +USB_P -USB_N
differential pair FTDI_USB: +FTDI_USB_P -FTDI_USB_N
differential pair AT_USB: +AT_USB_P -AT_USB_N
differential pair DFSD: +DFSD_P -DFSD_N

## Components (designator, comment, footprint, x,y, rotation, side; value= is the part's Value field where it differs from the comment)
A1 "PCB MIFA Antenna" MIFA_AMBIQ 3839.02,1301.32 r270 top net-tie
BTN0 "KFC-D003(4.3mm)" TACT_TOP 2890,215 r90 top
BTN1 "KFC-D003(4.3mm)" TACT_TOP 3194,215 r90 top
BTN2 "KFC-D003(4.3mm)" TACT_TOP 3500,215 r90 top locked
BTN3 "KFC-D003(4.3mm)" TACT_TOP 890.74,213 r90 top locked
C1 "1uF" CAPC0603L 3241,1173 r180 bottom
C2 "1uF" CAPC0603L 3148,1242 r90 bottom
C3 "1uF" CAPC0603L 3175,1242 r270 bottom
C4 "1uF" CAPC0603L 3189.07,1287.7 r0 bottom
C5 "2.2uF" CAPC0603L 3241,1201 r180 bottom
C6 "470nF" CAPC0603L 3145,1175 r180 bottom
C7 "2.2uF" CAPC0603L 3188.31,1147.04 r0 bottom
C8 "2.2uF" CAPC0603L 3188.07,1174.46 r0 bottom
C9 "2.2uF" CAPC0603L 3202,1242 r270 bottom
C10 "100nF" CAPC1005L 1445,763 r90 top
C11 "100nF" CAPC1005L 1894,1057 r180 top
C12 "100nF" CAPC1005L 1589,1508 r270 top
C13 "100nF" CAPC1005L 1149,1148 r0 top
C14 "100nF" CAPC1005L 1149,1181 r0 top
C15 "100nF" CAPC1005L 1149,1115 r0 top
C16 "100nF" CAPC1005L 1557,1508 r270 top
C17 "100nF" CAPC1005L 1894,1096 r180 top
C18 "100nF" CAPC1005L 1700,763 r90 top
C19 "100nF" CAPC1005L 1426,1536 r270 top
C20 "100nF" CAPC1005L 1894,1273 r180 top
C21 "100nF" CAPC1005L 1150,1328 r0 top
C22 "100nF" CAPC1005L 1285,760 r90 top
C23 "4.7uF" CAPC1005L 1793,1508 r270 top
C24 "100nF" CAPC1005L 1761,1508 r270 top
C25 "100nF" CAPC1005L 1729,1508 r270 top
C26 "10nF" CAPC1005L 1894,1313 r180 top
C27 "18pF" CAPC1005L 1389.72,1535.86 r270 top
C28 "18pF" CAPC1005L 1187.72,1537.18 r90 top
C29 "10pF" CAPC1005L 1229,1467 r180 top
C30 "100nF" CAPC1005L 373.23,1329.99 r0 top
C31 "1uF" CAPC1005L 373.23,1362.99 r0 top
C32 "4.7uF" CAPC1005L 555.23,1352.99 r180 top
C33 "10uF" CAPC1608N 810,1490 r180 top
C34 "1uF" CAPC1005L 271,885 r90 top
C35 "1uF" CAPC1005L 456,885 r90 top
C36 "1uF" CAPC1005L 905,1375 r270 top
C37 "4.7uF" CAPC0603L 3241,1230 r180 bottom
C38 "1uF" CAPC0603L 3240.81,1287.7 r180 bottom
C39 "NC" CAPC1005L 3265,1355 r90 top
C40 "GRM1555C1HR50BA01D" CAPC1005L 3330,1355.31 r90 top
C41 "GRM1555C1H4R3BA01D" CAPC1005L 3774,1301 r0 top
C42 "GRM1555C1H1R8CA01D" CAPC1005L 3793,1252 r270 top
C43 "NC" CAPC0603L 3286.81,1256.7 r0 bottom
C44 "NC" CAPC0603L 3285.81,1204.7 r180 bottom
C45 "47nF" CAPC0603L 3240.79,1256.7 r180 bottom
C46 "NC" CAPC0603L 3145,1048 r180 top
C47 "NC" CAPC0603L 3191,1048 r0 top
C48 "4.7uF" CAPC1005L 529,851 r90 top
C49 "4.7uF" CAPC1005L 1150,989 r0 top
C50 "1uF" CAPC1005L 510,751 r180 top
C51 "1uF" CAPC1005L 589,752 r0 top
C54 "220nF" CAPC1005L 586.03,985 r270 top
C55 "15pF" CAPC1005L 850,850 r270 top
C56 "15pF" CAPC1005L 710,850 r270 top
C57 "1uF" CAPC1005L 826,956 r270 bottom
C58 "1uF" CAPC1005L 804,1245 r270 top
C59 "100nF" CAPC1005L 973,937 r180 top
C60 "100nF" CAPC1005L 675,850 r90 top
C61 "100nF" CAPC1005L 630,1064.69 r270 top
C62 "100nF" CAPC1005L 768,1245 r270 top
C63 "100nF" CAPC1005L 917,1245 r270 top
C64 "100nF" CAPC1005L 949,1076 r270 top
C65 "4.7uF" CAPC1005L 880,1245 r270 top
C66 "470nF" CAPC1005L 811,459 r90 bottom
C67 "15pF" CAPC1005L 885,850 r90 top
C68 "15pF" CAPC1005L 1040,850 r90 top
C69 "100nF" CAPC1005L 915,570 r270 bottom
C70 "1uF" CAPC1005L 880,570 r270 bottom
C71 "100nF" CAPC1005L 715,750 r270 bottom
C72 "1uF" CAPC1005L 750,750 r270 bottom
C73 "100nF" CAPC1005L 750,670.31 r90 bottom
C74 "DNP" CAPC1005L 715,670 r90 bottom
C78 "1nF" CAPC1005L 745.5,1663.9 r0 top
C79 "100nF" CAPC1005L 950.5,1713.9 r180 top
C80 "100nF" CAPC1005L 950.5,1663.9 r0 top
C81 "1uF" CAPC1005L 1030.5,1578.9 r0 top
C82 "100nF" CAPC1005L 1110.5,1578.9 r180 top
C83 "1uF" CAPC1005L 970.5,1598.9 r90 top
C84 "100nF" CAPC1005L 930.5,1598.9 r90 top
D1 "PRTR5V0U2X" SOT143L 417,1150 r90 top locked
D2 "BLUE" LEDC1608L 104,1414 r0 top
D3 "BLUE" LEDC1608L 416,68 r90 top
D5 "BLUE" LEDC1608L 2745,580 r0 top
D6 "BLUE" LEDC1608L 2885,580 r0 top
D7 "BLUE" LEDC1608L 3025,580 r0 top
D8 "BLUE" LEDC1608L 3165,580 r0 top
D9 "BLUE" LEDC1608L 3305,580 r0 top
D70 "1N5819" SOD2512X100L 1020.5,1673.9 r270 top
FB1 "BLM15HG601SN1D" FBDC1005L 315,1416 r90 top
J1 "PDS127-230961SR-10" FTSH-105 3912,439 r90 top locked
J2 "PDS127-230961SR-10" FTSH-105 260,145 r0 top locked
J3 "TC2050-IDC" TC2050-IDC 2100,1515 r90 top locked
J5 "MM8430-2610RA1" MM8430-2610RA1 3465,1300 r90 top
L1 "2.2uH" BRC2012 3272,1092 r0 top
L2 "1.0uH" DFE18SAN 3302.81,1165.7 r180 top
L3 "LQG15HS2N7S02D" INDC1005L 3283.25,1301.32 r0 top
L4 "LQG15HS2N0S02D" INDC1005L 3348.63,1301.32 r0 top
L5 "LQG15HS4N3S02D" INDC1005L 3754,1252 r90 top
P1 "Header 1X10" HEADER1X10 1190,1950 r180 top locked
P2 "Header 1X10" HEADER1X10 1190,2350 r180 top locked
P3 "Header 1X8" HEADER1X8 1450,50 r0 top locked
P4 "Header 1X8" HEADER1X8 1450,350 r0 top locked
P5 "Header 1X8" HEADER1X8 2150,1950 r180 top locked
P6 "Header 1X8" HEADER1X8 2150,2349.99 r180 top locked
P7 "Header 1X8" HEADER1X8 2350,50 r0 top locked
P8 "Header 1X8" HEADER1X8 2350,350 r0 top locked
P9 "Header 1X8" HEADER1X8 3050,1950 r180 top locked
P10 "Header 1X8" HEADER1X8 3050,2349.99 r180 top locked
P11 "SSM-110-L-DV-P-TR" SSM-110-L-DV-TR 1190,2150 r180 top locked
P12 "SSM-108-L-SV-P-TR" SSM-108-L-SV-TR 1450,200 r180 top locked
P13 "SSM-108-L-DV-P-TR" SSM-108-L-DV-TR 2150,2150 r180 top locked
P14 "SSM-108-L-SV-P-TR" SSM-108-L-SV-TR 2350,200 r180 top locked
P15 "TSM-104-04-F-DV-P-TR" TSM-104-04-F-DV-TR 2555.51,1150 r90 top locked
P16 "TSM-104-04-F-DV-P-TR" TSM-104-04-F-DV-TR 3650,900 r90 top locked
P17 "SSM-108-L-DV-P-TR" SSM-108-L-DV-TR 3050,2150 r180 top locked
P18 "SSM-107-L-DV-P-TR" SSM-107-L-DV-TR 3747.02,1800 r90 top locked
P19 "TSM-104-04-F-DV-P-TR" TSM-104-04-F-DV-TR 275,1728.25 r180 top locked
P20 "TSM-104-04-F-DV-P-TR" TSM-104-04-F-DV-TR 275,576.25 r180 top locked
P21 "FIDUCIAL" Fiducial 3937.01,118.11 r0 top
P22 "FIDUCIAL" Fiducial 511.81,2322.83 r0 top
P23 "TYPE-C-31-M-12" TYPE-C-31-M-12 206,1150 r270 top locked
Q1 "CJ3400" SOT23-3L 2745,675 r270 top
Q2 "CJ3400" SOT23-3L 2885,675 r270 top
Q3 "CJ3400" SOT23-3L 3025,675 r270 top
Q4 "CJ3400" SOT23-3L 3165,675 r270 top
Q5 "CJ3400" SOT23-3L 3307.07,675 r270 top
Q6 "MMBT3904LT1G" SOT23-3N 1125.5,1673.9 r0 top
Q7 "MMBT3904LT1G" SOT23-3L 550,526.25 r90 top
Q11 "CJ3401" SOT23-3L 630,720 r270 bottom
Q12 "CJ3401" SOT23-3L 960,725 r270 bottom
Q13 "CJ3400" SOT23-3L 630,890 r270 bottom
R1 "10K" RESC1005L 3600,660 r90 top
R2 "10K" RESC1005L 3700,660 r90 top
R3 "10K" RESC1005L 3994,274 r90 top
R4 "100R" RESC1005L 1140,1786.25 r270 top
R5 "100R" RESC1005L 3216,1478 r270 top
R6 "150R" RESC1005L 1542,763 r90 top
R7 "150R" RESC1005L 1602,763 r90 top
R8 "4K7" RESC1005L 1828,1508 r90 top
R9 "150R" RESC1005L 1894,980 r180 top
R10 "4K7" RESC1005L 1659,1508 r90 top
R11 "4K7" RESC1005L 1695,1508 r90 top
R12 "4K7" RESC1005L 1623,1508 r270 top
R13 "1K" RESC1005L 1894,1234 r180 top
R14 "6K8" RESC1005L 1149,1467 r180 top
R15 "39R" RESC1005L 1149.69,1290 r180 top
R16 "39R" RESC1005L 1150,1250 r180 top
R17 "4K7" RESC1005L 373.23,1397.99 r0 top
R18 "10K" RESC1005L 373.23,1434.99 r180 top
R19 "2K2" RESC1005L 373.23,1471.99 r180 top
R20 "44K2" RESC1005L 555.23,1388.99 r0 top
R21 "1K07 1%" RESC1005L 620,1465 r270 top
R22 "1K2 1%" RESC1005L 710,1465 r270 top
R23 "4K53 1%" RESC1005L 575,1465 r270 top
R26 "51K" RESC1005L 730,1245 r270 top
R27 "1K" RESC1005L 325,341 r90 top
R28 "100K" RESC1005L 2720,780 r0 top
R29 "0R" RESC0603L 3332,1218 r270 top
R30 "100K" RESC1005L 2855,780 r0 top
R31 "1K" RESC1005L 2815,565 r270 top
R32 "1K" RESC1005L 2954,565 r270 top
R33 "1K" RESC1005L 3095,565 r270 top
R34 "1K" RESC1005L 3235,565 r270 top
R35 "1K" RESC1005L 3375,565 r270 top
R36 "100K" RESC1005L 2979,448 r90 top
R37 "100K" RESC1005L 3282,450 r90 top
R38 "100K" RESC1005L 3590,455 r90 top
R39 "100K" RESC1005L 2995,780 r0 top
R40 "100K" RESC1005L 3135,780 r0 top
R41 "100K" RESC1005L 3280,780 r0 top
R42 "10K" RESC1005L 550,442 r180 top
R43 "5K1" RESC1005L 417,1055 r180 top
R44 "5K1" RESC1005L 420,1244 r180 top
R45 "51K" RESC1005L 842,1245 r90 top
R46 "100K" RESC1005L 543,985 r90 top
R47 "51K" RESC1005L 630,985 r270 top
R48 "51K" RESC1005L 588,1146 r270 top
R49 "12K 1%" RESC1005L 859,956 r270 bottom
R50 "51K" RESC1005L 629,1146 r90 top
R51 "51K" RESC1005L 630,850 r90 top
R52 "12K 1%" RESC1005L 820,750.32 r90 bottom
R53 "10K" RESC1005L 770,459 r270 bottom
R54 "47K" RESC1005L 813,570 r90 bottom
R55 "10K" RESC1005L 893,459 r90 bottom
R56 "10K" RESC1005L 851,459 r90 bottom
R57 "10K" RESC1005L 728,459 r270 bottom
R58 "1M" RESC1005L 961.89,812.13 r180 bottom
R59 "47K" RESC1005L 585,850 r90 top
R60 "30K 1%" RESC1005L 665,1465 r90 top
R61 "20K 1%" RESC1005L 665,1375 r270 top
R62 "10K" RESC1005L 710,1375 r90 top
R79 "10K" RESC1005L 745.5,1713.9 r0 top
R80 "51R" RESC1005L 825.5,1618.9 r0 top
R81 "16K9" RESC1005L 825.5,1578.9 r0 top
R82 "10K" RESC1005L 890.5,1598.9 r90 top
R86 "1M" RESC1005L 1245,760 r270 top
SB1 "SBS" SBS 597,1537 r180 top net-tie
SB3 "SBS" SBS 1005,525 r0 top net-tie
SB4 "SBO" SBO 1115,925 r0 top
SB5 "SBS" SBS 1115,850 r0 top net-tie
SB6 "SBO" SBO 1115.53,765 r180 top
SB7 "SBS" SBS 1320,690 r270 top net-tie
SB8 "SBS" SBS 1570,695 r270 top net-tie
SB9 "SBS" SBS 2097,951.51 r0 top net-tie
SB10 "SBS" SBS 1822.57,691 r270 top net-tie
SB11 "SBS" SBS 2100,1150 r90 top net-tie
SB12 "SBS" SBS 2175,1200 r90 top net-tie
SB13 "SBS" SBS 2175,1100 r90 top net-tie
SB14 "SBS" SBS 2100,1050 r90 top net-tie
SB15 "SBO" SBO 44,1734.6 r90 top
SB16 "SBO" SBO 45,590.6 r90 top
SB17 "SBS" SBS 1005,590 r0 top net-tie
SB18 "SBS" SBS 1005,655 r0 top net-tie
SB19 "SBS" SBS 2787.5,778 r270 top net-tie
SB20 "SBS" SBS 2924,778 r270 top net-tie
SB21 "SBS" SBS 3061,778 r270 top net-tie
SB22 "SBS" SBS 3202,778 r270 top net-tie
SB23 "SBS" SBS 3345,775 r270 top net-tie
SB24 "SBS" SBS 2889,425 r0 top net-tie
SB25 "SBS" SBS 3194,426 r0 top net-tie
SB26 "SBS" SBS 3512,419 r0 top net-tie
SB27 "SBS" SBS 1005,715 r0 top net-tie
SB84 "SBS" SBS 1113.3,685 r0 top net-tie
SB85 "SBO" SBO 1115,600 r0 top
SW1 "SS-3235S" JS202011SCQN 230.57,2191.27 r180 top
TP1 "Test Point" TP_TH_10_20#1 550,371 r0 top
TP2 "Test Point" TP_TH_10_20#2 709,88 r0 top
TP3 "Test Point" TP_TH_10_20#3 518.98,68.23 r0 top
TP4 "Test Point" TP_TH_10_20#4 720.67,383.35 r0 top
TP6 "5016" 5016 3225,943 r180 top
TP7 "5016" 5016 1368,1705 r0 top
TP8 "5016" 5016 2809,1442 r0 top
U1 "APOLLO3BP" BGA104C40P12X9_530X430X80L 3141.7,1240.45 r0 top locked
U2 "74LVC1G3157GW" SOT363-6L 1294.84,596.18 r90 top
U3 "74LVC1G3157GW" SOT363-6L 1545,594.33 r90 top
U4 "74LVC1G3157GW" SOT363-6L 1796.98,596.18 r90 top
U5 "ATSAM3U2CA-AU" SQFP50P1600X1600-100L 1523.37,1135.79 r90 top locked
U6 "NCP380LMUAJAATBG" UDFN-6 464.91,1389 r270 top
U7 "SN74LVC2G04DCK" SOT363-6L 664,480 r270 top
U8 "LD39100PUR" DFN6 810,1390 r180 top
U9 "MAX44263AXA+T" SC-70-8 850.5,1688.9 r0 top
U11 "MIC5504-3.3YM5-TR" SOT23-5_L 364.24,870 r0 top
U12 "MIC5504-3.3YM5-TR" SOT23-5_L 553,665 r0 top
U13 "USB2512B-AEZG-TR" QFN50P600X600-36V4L 795,1050 r180 top locked
U14 "FT4222HQ-D-T" QFN50P500X500-32W2N 824.21,638.43 r90 top locked
X1 "ABS06W-32.678kHz-D-2-T" ABS06W 3166,1094 r180 top
X2 "7M-12.000MAAJ-T" OSCCC250X320X100L 1288.72,1556.18 r90 top
X3 "520-ECS-320-8-47JTNT" ECX-1247 3286.81,1239.7 r90 top
X4 "ABM11W-24.0000MHz-8" OSCCC160X200X100 780,850 r0 top
X5 "ABM10-167-12.000MHZ-T3" OSCCC200X250X100 961.89,851.5 r0 top

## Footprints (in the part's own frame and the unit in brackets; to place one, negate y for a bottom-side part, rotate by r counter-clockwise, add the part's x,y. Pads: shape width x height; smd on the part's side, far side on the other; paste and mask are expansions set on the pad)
5016 [mm]
  rect 4.7x3.4 smd: 1(0,0)
  body extent -1.92,-1.4 1.89,1.46, height 2.3
ABS06W [mm]
  rect 0.7x1.4 smd: 1(-0.75,0) 2(0.75,0)
  body extent -1,-0.61 1,0.61, height 0.6
BGA104C40P12X9_530X430X80L [mm] "BGA, 104-Leads, Body 5.30x4.30mmx0.80mm, Pitch 0.40mm"
  round 0.17 smd mask+0.038: A1(2.2,-1.6) A2(1.8,-1.6) A3(1.4,-1.6) A4(1,-1.6) A5(0.6,-1.6) A6(0.2,-1.6) A7(-0.2,-1.6) A8(-0.6,-1.6) A9(-1,-1.6) A10(-1.4,-1.6) A11(-1.8,-1.6) A12(-2.2,-1.6) B1(2.2,-1.2) B2(1.8,-1.2) B3(1.4,-1.2) B4(1,-1.2) B5(0.6,-1.2) B6(0.2,-1.2) B7(-0.2,-1.2) B8(-0.6,-1.2) B9(-1,-1.2) B10(-1.4,-1.2) B11(-1.8,-1.2) B12(-2.2,-1.2) C1(2.2,-0.8) C2(1.8,-0.8) C3(1.4,-0.8) C4(1,-0.8) C5(0.6,-0.8) C6(0.2,-0.8) C7(-0.2,-0.8) C8(-0.6,-0.8) C9(-1,-0.8) C10(-1.4,-0.8) C11(-1.8,-0.8) C12(-2.2,-0.8) D1(2.2,-0.4) D2(1.8,-0.4) D3(1.4,-0.4) D4(1,-0.4) D5(0.6,-0.4) D6(0.2,-0.4) D7(-0.2,-0.4) D8(-0.6,-0.4) D9(-1,-0.4) D10(-1.4,-0.4) D11(-1.8,-0.4) D12(-2.2,-0.4) E1(2.2,0) E2(1.8,0) E3(1.4,0) E4(1,0) E9(-1,0) E10(-1.4,0) E11(-1.8,0) E12(-2.2,0) F1(2.2,0.4) F2(1.8,0.4) F3(1.4,0.4) F4(1,0.4) F5(0.6,0.4) F6(0.2,0.4) F7(-0.2,0.4) F8(-0.6,0.4) F9(-1,0.4) F10(-1.4,0.4) F11(-1.8,0.4) F12(-2.2,0.4) G1(2.2,0.8) G2(1.8,0.8) G3(1.4,0.8) G4(1,0.8) G5(0.6,0.8) G6(0.2,0.8) G7(-0.2,0.8) G8(-0.6,0.8) G9(-1,0.8) G10(-1.4,0.8) G11(-1.8,0.8) G12(-2.2,0.8) H1(2.2,1.2) H2(1.8,1.2) H3(1.4,1.2) H4(1,1.2) H5(0.6,1.2) H6(0.2,1.2) H7(-0.2,1.2) H8(-0.6,1.2) H9(-1,1.2) H10(-1.4,1.2) H11(-1.8,1.2) H12(-2.2,1.2) J1(2.2,1.6) J2(1.8,1.6) J3(1.4,1.6) J4(1,1.6) J5(0.6,1.6) J6(0.2,1.6) J7(-0.2,1.6) J8(-0.6,1.6) J9(-1,1.6) J10(-1.4,1.6) J11(-1.8,1.6) J12(-2.2,1.6)
  silkscreen extent -2.65,-2.15 2.65,2.15, body extent -2.65,-2.15 2.65,2.15, height 0.8
BRC2012 [mm]
  rect 0.6x1.45 smd: 1(-0.8,0) 2(0.8,0)
  body extent -1.05,-0.75 1.05,0.75, height 1.7
CAPC0603L [mm] "Chip Capacitor, Body 1.0x0.5mm, IPC High Density"
  rect 0.36x0.32 smd mask+0.102: 1(-0.28,0)
  rect 0.36x0.32 smd: 2(0.28,0)
  body extent -0.3,-0.16 0.3,0.16, height 0.31
CAPC1005L [mm] "Chip Capacitor, Body 1.0x0.5mm, IPC High Density"
  rect 0.6x0.5 smd: 1(-0.5,0) 2(0.5,0)
  body extent -0.5,-0.26 0.5,0.26, height 0.51
CAPC1608N [mm] "Chip Capacitor, Body 1.6x0.8mm, IPC Medium Density"
  rect 1x1 smd: 1(-0.8,0) 2(0.8,0)
  body extent -0.8,-0.41 0.8,0.41, height 0.81
DFE18SAN [mm]
  rect 0.8x0.9 smd: 1(-0.7,0) 2(0.7,0)
  body extent -0.8,-0.4 0.8,0.4, height 0.8
DFN6 [mm] "3x3"
  rect 0.55x0.45 smd: 1(-1.375,0.95) 2(-1.375,0) 3(-1.375,-0.95) 4(1.375,-0.95) 5(1.375,0) 6(1.375,0.95)
  rect 1.7x2.5 smd: 7(0,0)
  silkscreen extent -1.6,1.45 -1.5,1.55, body extent -1.55,-1.5 1.55,1.5, height 0.8
ECX-1247 [mm]
  rect 0.75x0.65 smd: 1(-0.525,-0.375) 2(0.525,-0.375) 3(0.525,0.375) 4(-0.525,0.375)
  body extent -1.02,-0.6 0.8,0.6, height 0.61
FBDC1005L [mm] "Ferrite Bead, Body 1.1x0.5mm, IPC High Density"
  rect 0.6x0.6 smd: 1(-0.5,0) 2(0.5,0)
  body extent -0.5,-0.25 0.5,0.25, height 0.5
Fiducial [mm]
  round 1 smd: 1(0,0)
  round 3 on Top Solder: 3(0,0)
  Layer 1 keep-out circle w0.02: c0,0 r1.5
FTSH-105 [mm]
  rect 0.76x2.4 smd: 1(2.54,1.95) 2(2.54,-1.95) 3(1.27,1.95) 4(1.27,-1.95) 5(0,1.95) 6(0,-1.95) 7(-1.27,1.95) 8(-1.27,-1.95) 9(-2.54,1.95) 10(-2.54,-1.95)
  silkscreen extent 2.41,3.43 2.67,3.68, body extent -3.18,-2.92 3.17,2.92, height 6.11
HEADER1X8 [mm]
  rect 1.5x1.5 hole 0.9: 1(-8.89,0)
  round 1.5 hole 0.9: 2(-6.35,0) 3(-3.81,0) 4(-1.27,0) 5(1.27,0) 6(3.81,0) 7(6.35,0) 8(8.89,0)
  body extent -10.16,-1.27 10.16,1.27, height 8.54
HEADER1X10 [mm]
  rect 1.5x1.5 hole 0.9: 1(-11.43,0)
  round 1.5 hole 0.9: 2(-8.89,0) 3(-6.35,0) 4(-3.81,0) 5(-1.27,0) 6(1.27,0) 7(3.81,0) 8(6.35,0) 9(8.89,0) 10(11.43,0)
  body extent -12.7,-1.27 12.7,1.27, height 8.54
INDC1005L [mm] "Chip Inductor, Body 1.0x0.5mm, IPC High Density"
  rect 0.7x0.6 smd: 1(-0.45,0) 2(0.45,0)
  body extent -0.5,-0.3 0.5,0.3, height 0.5
JS202011SCQN [mm]
  rect 1.2x2.5 smd: 1(-2.5,-2.75) 2(0,-2.75) 3(2.5,-2.75) 4(-2.5,2.75) 5(0,2.75) 6(2.5,2.75)
  silkscreen extent -4.5,-1.8 4.5,1.8, body extent -4.6,-3.5 4.6,3.5, height 3.6
LEDC1608L [mm] "Chip LED, Body 1.6x0.8mm, IPC High Density"
  rect 0.7x0.9 smd: 1(-0.75,0) 2(0.75,0)
  body extent -0.8,-0.4 0.8,0.4, height 0.61
MIFA_AMBIQ [mm]
  rect 0.2x0.1 smd: 1(0,0)
  Layer 1 region: -2.548,-0.608 -2.553,-0.607 -2.557,-0.604 -2.56,-0.6 -2.561,-0.595 -2.561,-0.595 -2.561,4.795 -2.56,4.8 -2.557,4.805 -2.553,4.807 -2.548,4.808 -2.548,4.808 2.452,4.808 2.457,4.807 2.461,4.805 2.464,4.8 2.465,4.795 2.465,4.795 2.465,2.168 4.439,2.168 4.439,4.795 4.44,4.8 4.443,4.805 4.447,4.807 4.452,4.808 4.452,4.808 7.152,4.808 7.157,4.807 7.161,4.805 7.164,4.8 7.165,4.795 7.165,4.795 7.165,2.168 9.139,2.168 9.139,4.795 9.14,4.8 9.143,4.805 9.147,4.807 9.152,4.808 9.152,4.808 11.852,4.808 11.857,4.807 11.861,4.805 11.864,4.8 11.865,4.795 11.865,4.795 11.865,2.362 11.339,2.362 11.339,4.282 9.665,4.282 9.665,1.655 9.664,1.65 9.661,1.646 9.657,1.643 9.652,1.642 9.652,1.642 6.652,1.642 6.647,1.643 6.643,1.646 6.64,1.65 6.639,1.655 6.639,1.655 6.639,4.282 4.965,4.282 4.965,1.655 4.964,1.65 4.961,1.646 4.957,1.643 4.952,1.642 4.952,1.642 1.952,1.642 1.947,1.643 1.943,1.646 1.94,1.65 1.939,1.655 1.939,1.655 1.939,4.282 0.265,4.282 0.265,-0.595 0.264,-0.6 0.261,-0.604 0.257,-0.607 0.252,-0.608 0.252,-0.608 -0.248,-0.608 -0.253,-0.607 -0.257,-0.604 -0.26,-0.6 -0.261,-0.595 -0.261,-0.595 -0.261,4.282 -1.635,4.282 -1.635,-0.595 -1.636,-0.6 -1.639,-0.604 -1.643,-0.607 -1.648,-0.608 -1.648,-0.608
MM8430-2610RA1 [mm]
  rect 1x0.5 smd: 1(0,1.75) 2(0,-1.75)
  rect 0.5x0.52 smd: 1(0,1.3) 2(0,-1.3)
  rect 1x1 smd: 3(-1.5,-1) 3(-1.5,1) 3(1.5,-1) 3(1.5,1)
  silkscreen extent -1.8,-2.06 1.78,2.06, body extent -1.5,-1.5 1.5,1.5, height 1.75
OSCCC160X200X100 [mm]
  rect 0.75x0.7 smd: 1(-0.675,-0.5) 2(0.675,-0.5) 3(0.675,0.5) 4(-0.675,0.5)
  body extent -1,-0.8 1,0.8, height 0.7
OSCCC200X250X100 [mm]
  rect 1x0.9 smd: 1(-0.81,-0.8) 2(0.81,-0.8) 4(-0.81,0.8)
  rect 1.1x0.9 smd: 3(0.81,0.8)
  body extent -1.25,-1 1.25,1, height 0.8
OSCCC250X320X100L [mm]
  rect 1.3x0.9 smd: 1(-0.85,1.4) 2(-0.85,-1.4) 3(0.85,-1.4) 4(0.85,1.4)
  body extent -1.25,-1.6 1.25,1.6, height 0.81
QFN50P500X500-32W2N [mm] "QFN, 32-Leads, Body 5x5mm, Pitch 0.5mm, IPC Medium Density"
  oval 0.8x0.3 smd: 1(-2.5,1.75) 2(-2.5,1.25) 3(-2.5,0.75) 4(-2.5,0.25) 5(-2.5,-0.25) 6(-2.5,-0.75) 7(-2.5,-1.25) 8(-2.5,-1.75) 17(2.5,-1.75) 18(2.5,-1.25) 19(2.5,-0.75) 20(2.5,-0.25) 21(2.5,0.25) 22(2.5,0.75) 23(2.5,1.25) 24(2.5,1.75)
  oval 0.3x0.8 smd: 9(-1.75,-2.5) 10(-1.25,-2.5) 11(-0.75,-2.5) 12(-0.25,-2.5) 13(0.25,-2.5) 14(0.75,-2.5) 15(1.25,-2.5) 16(1.75,-2.5) 25(1.75,2.5) 26(1.25,2.5) 27(0.75,2.5) 28(0.25,2.5) 29(-0.25,2.5) 30(-0.75,2.5) 31(-1.25,2.5) 32(-1.75,2.5)
  rect 3.3x3.3 smd: 33(0,0)
  silkscreen extent -3.57,-2.6 2.6,2.6, body extent -2.49,-2.51 2.53,2.51, height 0.8
QFN50P600X600-36V4L [mm] "QFN, 36-Leads, Body 6x6mm, Pitch 0.5mm, IPC High Density"
  oval 0.65x0.3 smd: 1(-2.975,2) 2(-2.975,1.5) 3(-2.975,1) 4(-2.975,0.5) 5(-2.975,0) 6(-2.975,-0.5) 7(-2.975,-1) 8(-2.975,-1.5) 9(-2.975,-2) 19(2.975,-2) 20(2.975,-1.5) 21(2.975,-1) 22(2.975,-0.5) 23(2.975,0) 24(2.975,0.5) 25(2.975,1) 26(2.975,1.5) 27(2.975,2)
  oval 0.3x0.65 smd: 10(-2,-2.975) 11(-1.5,-2.975) 12(-1,-2.975) 13(-0.5,-2.975) 14(0,-2.975) 15(0.5,-2.975) 16(1,-2.975) 17(1.5,-2.975) 18(2,-2.975) 28(2,2.975) 29(1.5,2.975) 30(1,2.975) 31(0.5,2.975) 32(0,2.975) 33(-0.5,2.975) 34(-1,2.975) 35(-1.5,2.975) 36(-2,2.975)
  rect 4.8x4.8 smd: 37(0,0)
  silkscreen extent -3.98,-3.1 3.1,3.1, body extent -3.08,-3.08 3.08,3.08, height 1
RESC0603L [mm] "Chip Resistor, Body 0.6x0.3mm, IPC High Density"
  rect 0.34x0.32 smd: 1(-0.29,0) 2(0.29,0)
  body extent -0.3,-0.15 0.3,0.15, height 0.23
RESC1005L [mm] "Chip Resistor, Body 1.1x0.5mm, IPC High Density"
  rect 0.6x0.6 smd: 1(-0.5,0) 2(0.5,0)
  body extent -0.5,-0.25 0.5,0.25, height 0.3
SBO [mil]
  rect 5x5 smd: 1(-10,0.04) 2(10,-0.04)
  Layer 1 region: 3.05,16.93 6.03,19.82 10.69,18.31 13.23,16.62 16.13,13.72 18.23,11.42 20.53,7.52 21.63,3.82 21.43,-4.88 20.43,-7.68 17.13,-13.08 13.83,-16.28 10.22,-18.54 6.23,-19.78 4.23,-19.08 3.05,-17.01 3.05,16.93
  Layer 1 region: -3.24,-16.93 -6.22,-19.82 -10.88,-18.31 -13.42,-16.62 -16.32,-13.72 -18.42,-11.42 -20.72,-7.52 -21.82,-3.82 -21.62,4.88 -20.62,7.68 -17.32,13.08 -14.02,16.28 -10.41,18.54 -6.42,19.78 -4.42,19.08 -3.24,17.01 -3.24,-16.93
SBS [mil]
  rect 5x5 smd: 1(-11.19,0) 2(11.19,-0.12)
  Layer 1 region: -4.02,-17.09 -7,-19.98 -11.66,-18.46 -14.2,-16.78 -17.1,-13.88 -19.2,-11.58 -21.5,-7.68 -22.6,-3.98 -22.4,4.72 -21.4,7.52 -18.1,12.92 -14.8,16.12 -11.19,18.39 -7.2,19.62 -5.2,18.92 -4.02,16.85 -4.02,-17.09
  Layer 1 region: 4.02,16.93 7,19.82 11.66,18.31 14.2,16.62 17.1,13.72 19.2,11.42 21.5,7.52 22.6,3.82 22.4,-4.88 21.4,-7.68 18.1,-13.08 14.8,-16.28 11.19,-18.54 7.2,-19.78 5.2,-19.08 4.02,-17.01 4.02,16.93
  Layer 1 lines w8: 13.3,0 -13.3,0
SC-70-8 [mil]
  rect 39x12 smd: 1(-35.43,29.53) 2(-35.43,9.84) 3(-35.43,-9.84) 4(-35.43,-29.53) 5(35.43,-29.53) 6(35.43,-9.84) 7(35.43,9.84) 8(35.43,29.53)
  silkscreen extent -64,-50 48,52, body extent -41,-39 41,39, height 35
SOD2512X100L [mm] "SOD Diode: SOD-323"
  rect 0.7x0.5 smd: 1(-1.2,0) 2(1.2,0)
  silkscreen extent -0.38,-0.55 -0.38,0.55, body extent -1.31,-0.67 1.34,0.63, height 1
SOT23-3L [mm] "SOT23, 3-Leads, Body 2.9x1.3mm, Pitch 0.95mm, Lead Span 2.5mm, IPC High Density"
  rect 1.2x0.6 smd: 1(-0.9,0.95) 2(-0.9,-0.95) 3(0.9,0)
  silkscreen extent 0.1,-1.5 0.7,1.5, body extent -1.29,-1.5 1.35,1.5, height 1.08
SOT23-3N [mm] "SOT23, 3-Leads, Body 2.9x1.3mm, Pitch 0.95mm, Lead Span 2.5mm, IPC Medium Density"
  rect 1.5x0.6 smd: 1(-0.95,0.95) 2(-0.95,-0.95) 3(0.95,0)
  silkscreen extent 0.2,-1.5 0.7,1.5, body extent -1.35,-1.5 1.29,1.5, height 1.08
SOT23-5_L [mm] "SOT23, 5-Leads, Body 2.9x1.6mm, Pitch 0.95mm, Lead Span 2.8mm, IPC High Density"
  rect 0.9x0.65 smd: 1(-1.2,0.95) 2(-1.2,0) 3(-1.2,-0.95) 4(1.2,-0.95) 5(1.2,0.95)
  silkscreen extent -0.35,-1.55 0.35,1.55, body extent -1.45,-1.47 1.35,1.43, height 1.09
SOT143L [mm] "SOT143, 4-Leads, Body 2.9x1.3mm, Pitch 1.9mm, Lead Span 2.5mm, IPC High Density"
  rect 1x1 smd: 1(-1,0.75)
  rect 1x0.6 smd: 2(-1,-0.95) 3(1,-0.95) 4(1,0.95)
  silkscreen extent -1.47,-1.5 0.3,1.92, body extent -1.21,-1.46 1.21,1.46, height 1
SOT363-6L [mm] "SOT363, 6-Leads, Body 2x1.3mm, Pitch 0.65mm, Lead Span 2.1mm, IPC High Density"
  rect 0.65x0.4 smd: 1(-0.95,0.65) 2(-0.95,0) 3(-0.95,-0.65) 4(0.95,-0.65) 5(0.95,0) 6(0.95,0.65)
  silkscreen extent -0.38,-1.1 0.25,1.1, body extent -1.15,-1.05 1.15,1.05, height 1
SQFP50P1600X1600-100L [mm] "Shrink QFP, 100-Leads, Body 14x14mm, Pitch 0.5mm, IPC High Density"
  oval 1.55x0.25 smd: 1(-7.525,6) 2(-7.525,5.5) 3(-7.525,5) 4(-7.525,4.5) 5(-7.525,4) 6(-7.525,3.5) 7(-7.525,3) 8(-7.525,2.5) 9(-7.525,2) 10(-7.525,1.5) 11(-7.525,1) 12(-7.525,0.5) 13(-7.525,0) 14(-7.525,-0.5) 15(-7.525,-1) 16(-7.525,-1.5) 17(-7.525,-2) 18(-7.525,-2.5) 19(-7.525,-3) 20(-7.525,-3.5) 21(-7.525,-4) 22(-7.525,-4.5) 23(-7.525,-5) 24(-7.525,-5.5) 25(-7.525,-6) 51(7.525,-6) 52(7.525,-5.5) 53(7.525,-5) 54(7.525,-4.5) 55(7.525,-4) 56(7.525,-3.5) 57(7.525,-3) 58(7.525,-2.5) 59(7.525,-2) 60(7.525,-1.5) 61(7.525,-1) 62(7.525,-0.5) 63(7.525,0) 64(7.525,0.5) 65(7.525,1) 66(7.525,1.5) 67(7.525,2) 68(7.525,2.5) 69(7.525,3) 70(7.525,3.5) 71(7.525,4) 72(7.525,4.5) 73(7.525,5) 74(7.525,5.5) 75(7.525,6)
  oval 0.25x1.55 smd: 26(-6,-7.525) 27(-5.5,-7.525) 28(-5,-7.525) 29(-4.5,-7.525) 30(-4,-7.525) 31(-3.5,-7.525) 32(-3,-7.525) 33(-2.5,-7.525) 34(-2,-7.525) 35(-1.5,-7.525) 36(-1,-7.525) 37(-0.5,-7.525) 38(0,-7.525) 39(0.5,-7.525) 40(1,-7.525) 41(1.5,-7.525) 42(2,-7.525) 43(2.5,-7.525) 44(3,-7.525) 45(3.5,-7.525) 46(4,-7.525) 47(4.5,-7.525) 48(5,-7.525) 49(5.5,-7.525) 50(6,-7.525) 76(6,7.525) 77(5.5,7.525) 78(5,7.525) 79(4.5,7.525) 80(4,7.525) 81(3.5,7.525) 82(3,7.525) 83(2.5,7.525) 84(2,7.525) 85(1.5,7.525) 86(1,7.525) 87(0.5,7.525) 88(0,7.525) 89(-0.5,7.525) 90(-1,7.525) 91(-1.5,7.525) 92(-2,7.525) 93(-2.5,7.525) 94(-3,7.525) 95(-3.5,7.525) 96(-4,7.525) 97(-4.5,7.525) 98(-5,7.525) 99(-5.5,7.525) 100(-6,7.525)
  silkscreen extent -7.65,-6.35 6.35,6.8, body extent -8,-8 8,8, height 1.45
SSM-107-L-DV-TR [mil]
  rect 50x145 smd mask+2: 1(298.48,-100) 2(300,100) 3(200,-99.01) 4(200,100) 5(100,-100) 6(100,100) 7(0,-100) 8(0,100) 9(-100,-100) 10(-100,100) 11(-200,-100) 12(-200,100) 13(-300,-100) 14(-300,100)
  rect 60x60 hole 35.43: 1(300,-50)
  rrect100% 60x60 hole 35.43: 2(300,50) 3(200,-50) 4(200,50) 5(100,-50) 6(100,50) 7(0,-50) 8(0,50) 9(-100,-50) 10(-100,50) 11(-200,-50) 12(-200,50) 13(-300,-50) 14(-300,50)
  body extent -350,-138 350,139, height 290
SSM-108-L-DV-TR [mil]
  rect 60x60 hole 35.43: 1(-350,50)
  rect 40.16x87.4 smd: 1(-350,111.26) 2(-350,-111.26) 3(-250,111.26) 4(-250,-111.26) 5(-150,111.26) 6(-150,-111.26) 7(-50,111.26) 8(-50,-111.26) 9(50,111.26) 10(50,-111.26) 11(150,111.26) 12(150,-111.26) 13(250,111.26) 14(250,-111.26) 15(350,111.26) 16(350,-111.26)
  round 60 hole 35.43: 2(-350,-50)
  rrect100% 60x60 hole 35.43: 3(-250,50) 4(-250,-50) 5(-150,50) 6(-150,-50) 7(-50,50) 8(-50,-50) 9(50,50) 10(50,-50) 11(150,50) 12(150,-50) 13(250,50) 14(250,-50) 15(350,50) 16(350,-50)
  body extent -400,-138 400,139, height 290
SSM-108-L-SV-TR [mm]
  rect 1.02x2.19 smd: 1(8.89,-1.465) 1(8.89,1.465) 2(6.35,-1.465) 2(6.35,1.465) 3(3.81,-1.465) 3(3.81,1.465) 4(1.27,1.465) 4(1.27,-1.465) 5(-1.27,1.465) 5(-1.27,-1.465) 6(-3.81,-1.465) 6(-3.81,1.465) 7(-6.35,-1.465) 7(-6.35,1.465) 8(-8.89,-1.465) 8(-8.89,1.465)
  rect 1.524x1.524 hole 0.9: 1(8.89,0)
  rrect100% 1.524x1.524 hole 0.9: 2(6.35,0) 3(3.81,0) 4(1.27,0) 5(-1.27,0) 6(-3.81,0) 7(-6.35,0) 8(-8.89,0)
  body extent -10.16,-2.29 10.16,2.29, height 7.52
SSM-110-L-DV-TR [mil]
  rect 60x60 hole 35.43: 1(-450,50)
  rect 40.16x87.4 smd: 1(-450,111.26) 2(-450,-111.26) 3(-350,111.26) 4(-350,-111.26) 5(-250,111.26) 6(-250,-111.26) 7(-150,111.26) 8(-150,-111.26) 9(-50,111.26) 10(-50,-111.26) 11(50,111.26) 12(50,-111.26) 13(150,111.26) 14(150,-111.26) 15(250,111.26) 16(250,-111.26) 17(350,111.26) 18(350,-111.26) 19(450,111.26) 20(450,-111.26)
  round 60 hole 35.43: 2(-450,-50)
  rrect100% 60x60 hole 35.43: 3(-350,50) 4(-350,-50) 5(-250,50) 6(-250,-50) 7(-150,50) 8(-150,-50) 9(-50,50) 10(-50,-50) 11(50,50) 12(50,-50) 13(150,50) 14(150,-50) 15(250,50) 16(250,-50) 17(350,50) 18(350,-50) 19(450,50) 20(450,-50)
  body extent -500,-138 500,139, height 290
TACT_TOP [mm] "Tact Switch Side Push"
  rect 1.5x1.4 smd mask+0: 1(-4.2,2.25) 2(-4.2,-2.25) 3(4.2,-2.25) 4(4.2,2.25)
  body extent -4.5,-3 4.5,3, height 4.25
TC2050-IDC [mil]
  round 39 smd paste-20: 1(-100,-25) 2(-50,-25) 3(0,-25) 4(50,-25) 5(100,-25) 6(100,25) 7(50,25) 8(0,25) 9(-50,25) 10(-100,25)
  round 39 hole 39 unplated: MH(-150,0) MH(150,-40) MH(150,40)
TP_TH_10_20#1 [mm]
  round 2 hole 1: 1(-0.254,-0.533)
TP_TH_10_20#2 [mm]
  round 2 hole 1: 1(-1.753,-0.203)
TP_TH_10_20#3 [mm]
  round 2 hole 1: 1(0.534,0.299)
TP_TH_10_20#4 [mm]
  round 2 hole 1: 1(-2.049,-0.847)
TSM-104-04-F-DV-TR [mil]
  rect 60x60 hole 35.43: 1(150,50)
  rect 50x145 smd mask+2: 1(150,100) 2(150,-100) 3(50,100) 4(50,-100) 5(-50,100) 6(-50,-100) 7(-150,100) 8(-150,-100)
  rrect100% 60x60 hole 35.43: 2(150,-50) 3(50,50) 4(50,-50) 5(-50,50) 6(-50,-50) 7(-150,50) 8(-150,-50)
  body extent -200,-151 200,152, height 378
TYPE-C-31-M-12 [mm]
  rect 0.3x1.3 smd: A1(-3.4,2.623) A4(-2.6,2.623) A5(-1.25,2.623) A6(-0.25,2.623) A7(0.25,2.623) A8(1.25,2.624) A9(2.6,2.623) A12(3.4,2.623) B1(3.1,2.623) B4(2.3,2.623) B5(1.75,2.623) B6(0.75,2.623) B7(-0.75,2.623) B8(-1.75,2.624) B9(-2.3,2.623) B12(-3.1,2.623)
  oval 1.2x2.1 hole 0.7 slot 1.7 at 90 deg: MH(-4.32,1.556) MH(4.32,1.556)
  oval 1.2x1.8 hole 0.7 slot 1.3 at 90 deg: MH(-4.32,-2.624) MH(4.32,-2.624)
  round 0.1 hole 0.7 unplated: MH(-2.89,1.026) MH(2.89,1.026)
  body extent -4.47,-5.25 4.47,2.65, height 3.21
UDFN-6 [mm]
  rect 0.4x0.47 smd: 1(0.65,0.915) 2(0,0.915) 3(-0.65,0.915) 4(-0.65,-0.915) 5(0,-0.915) 6(0.65,-0.915)
  rect 1.7x0.95 smd: 7(0,0)
  silkscreen extent 1.2,0.8 1.45,1.05, body extent -1,-1 1,1, height 2.29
